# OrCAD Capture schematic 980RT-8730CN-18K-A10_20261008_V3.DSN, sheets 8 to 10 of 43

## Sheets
8 P0021_S2_DUT1: size Custom
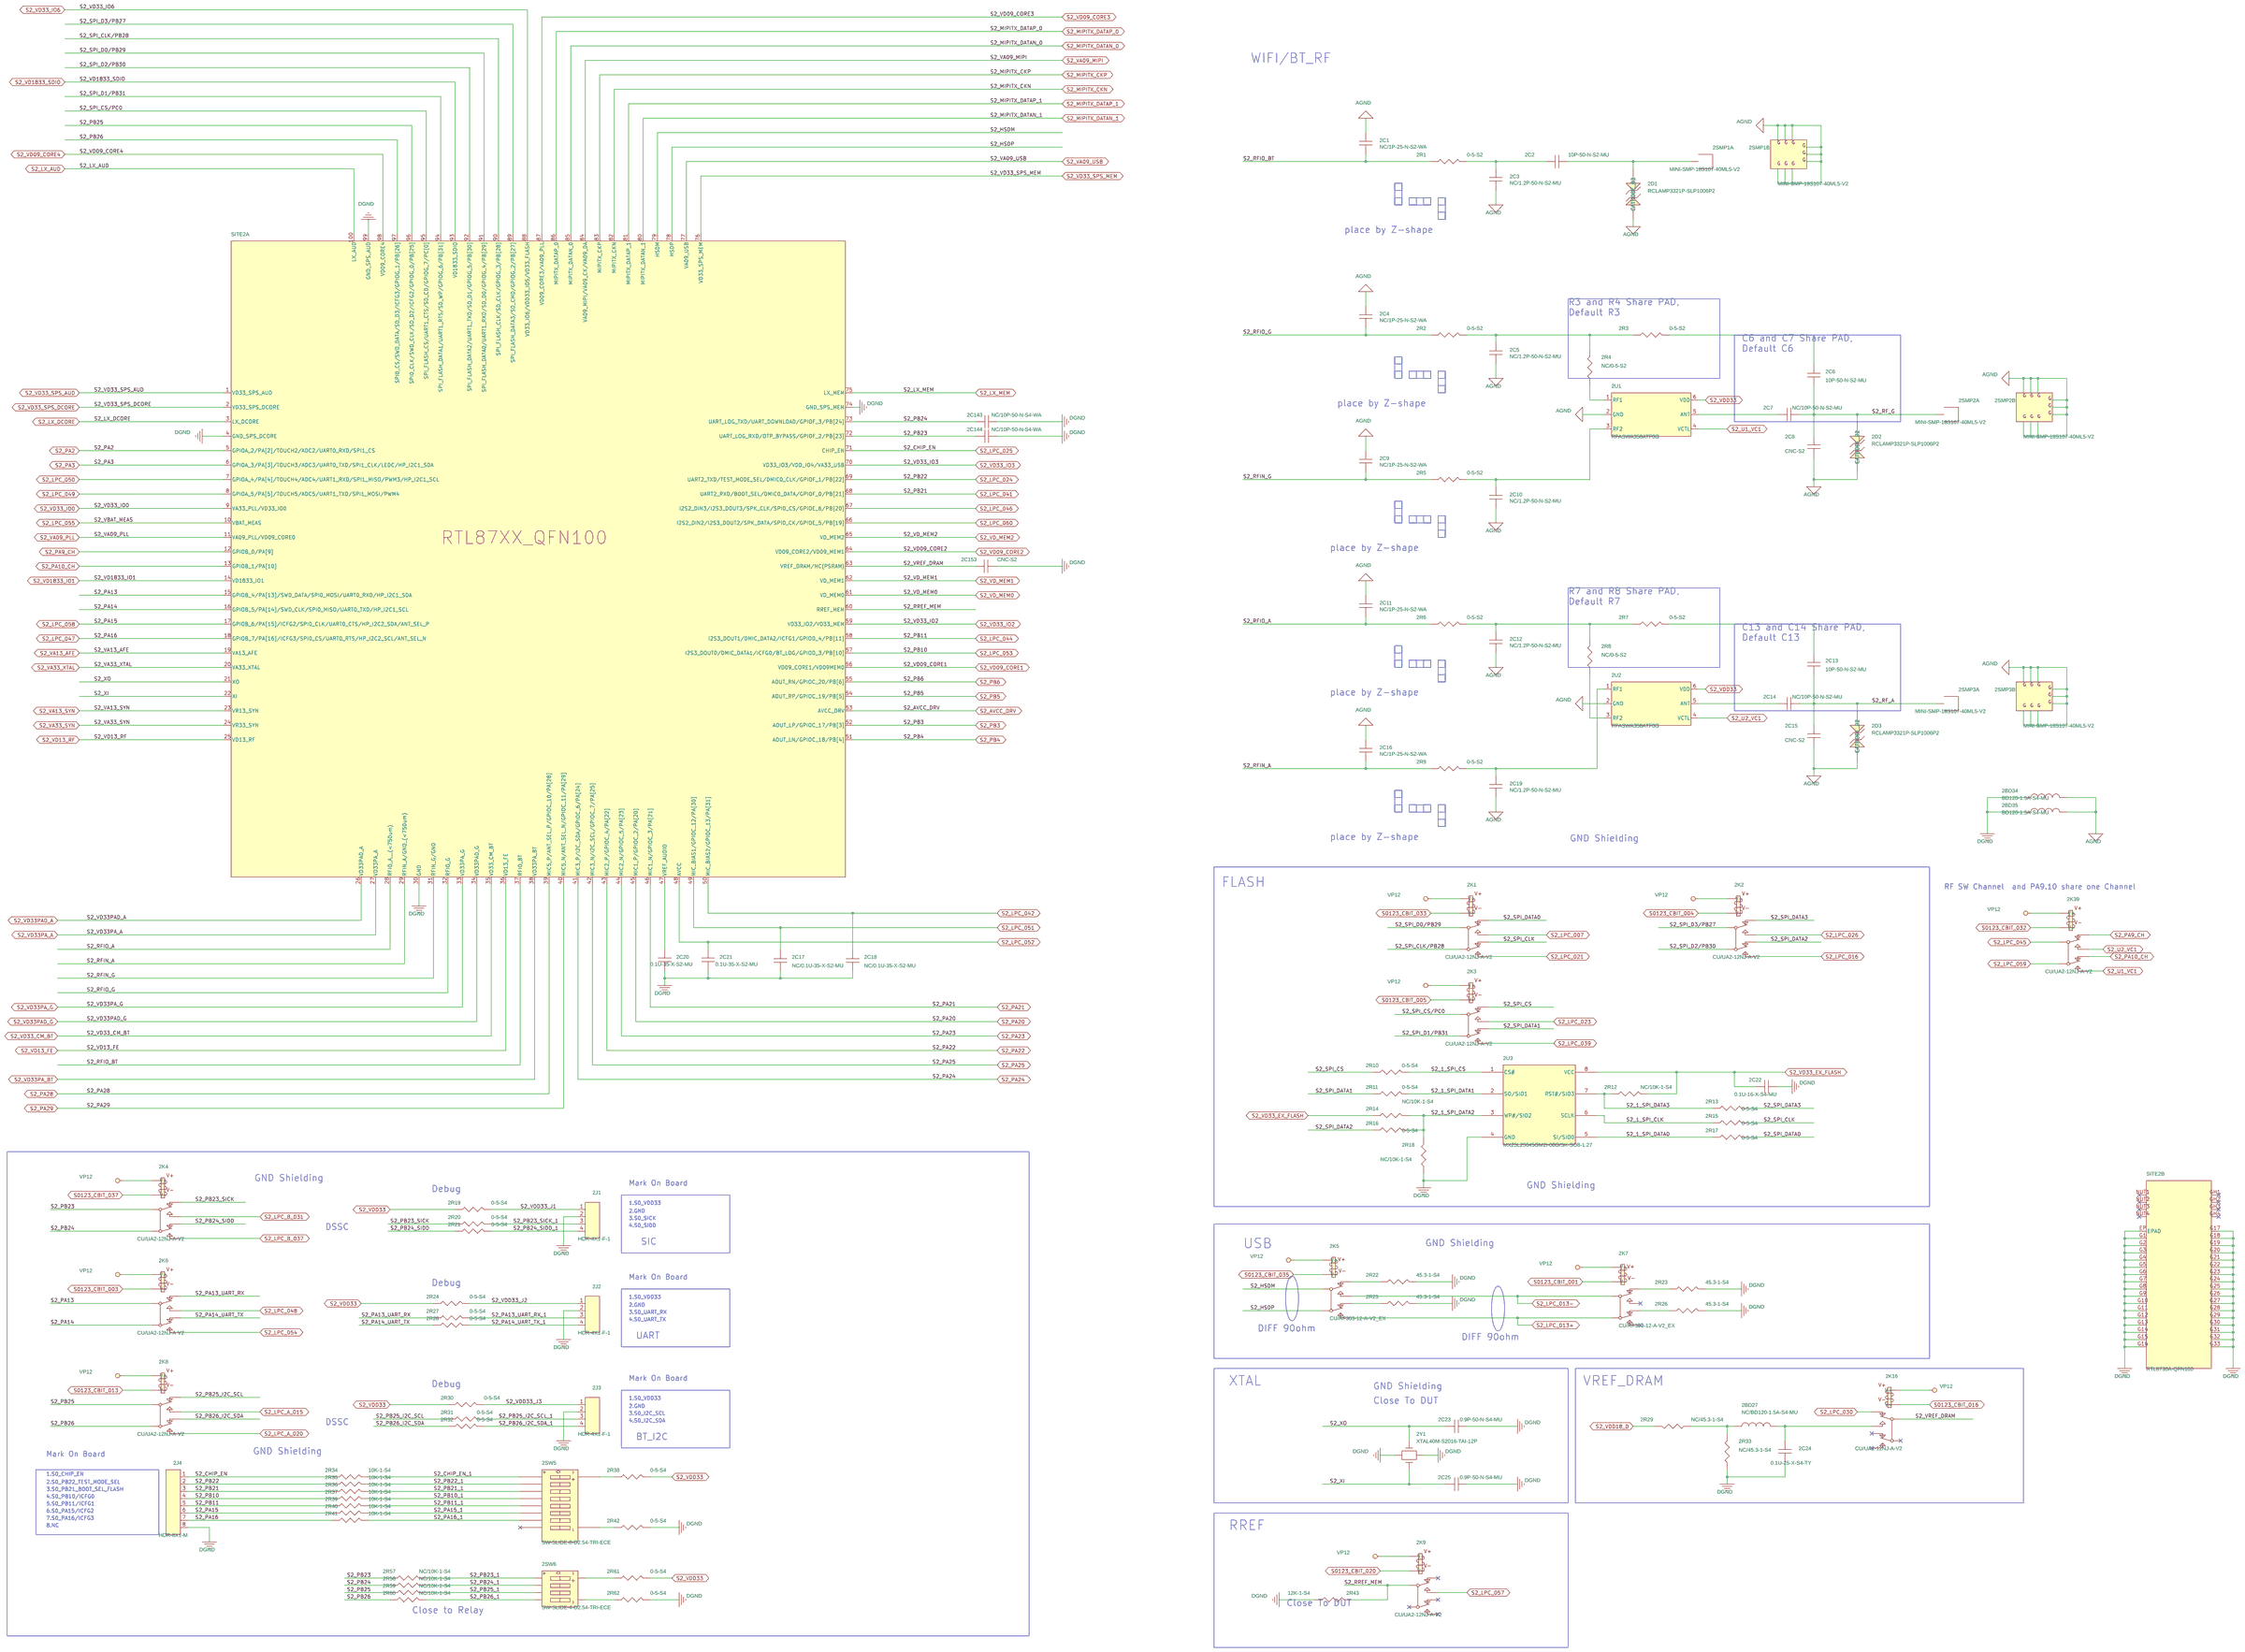
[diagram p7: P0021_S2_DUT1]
9 P0022_S2_Function-test: size A3
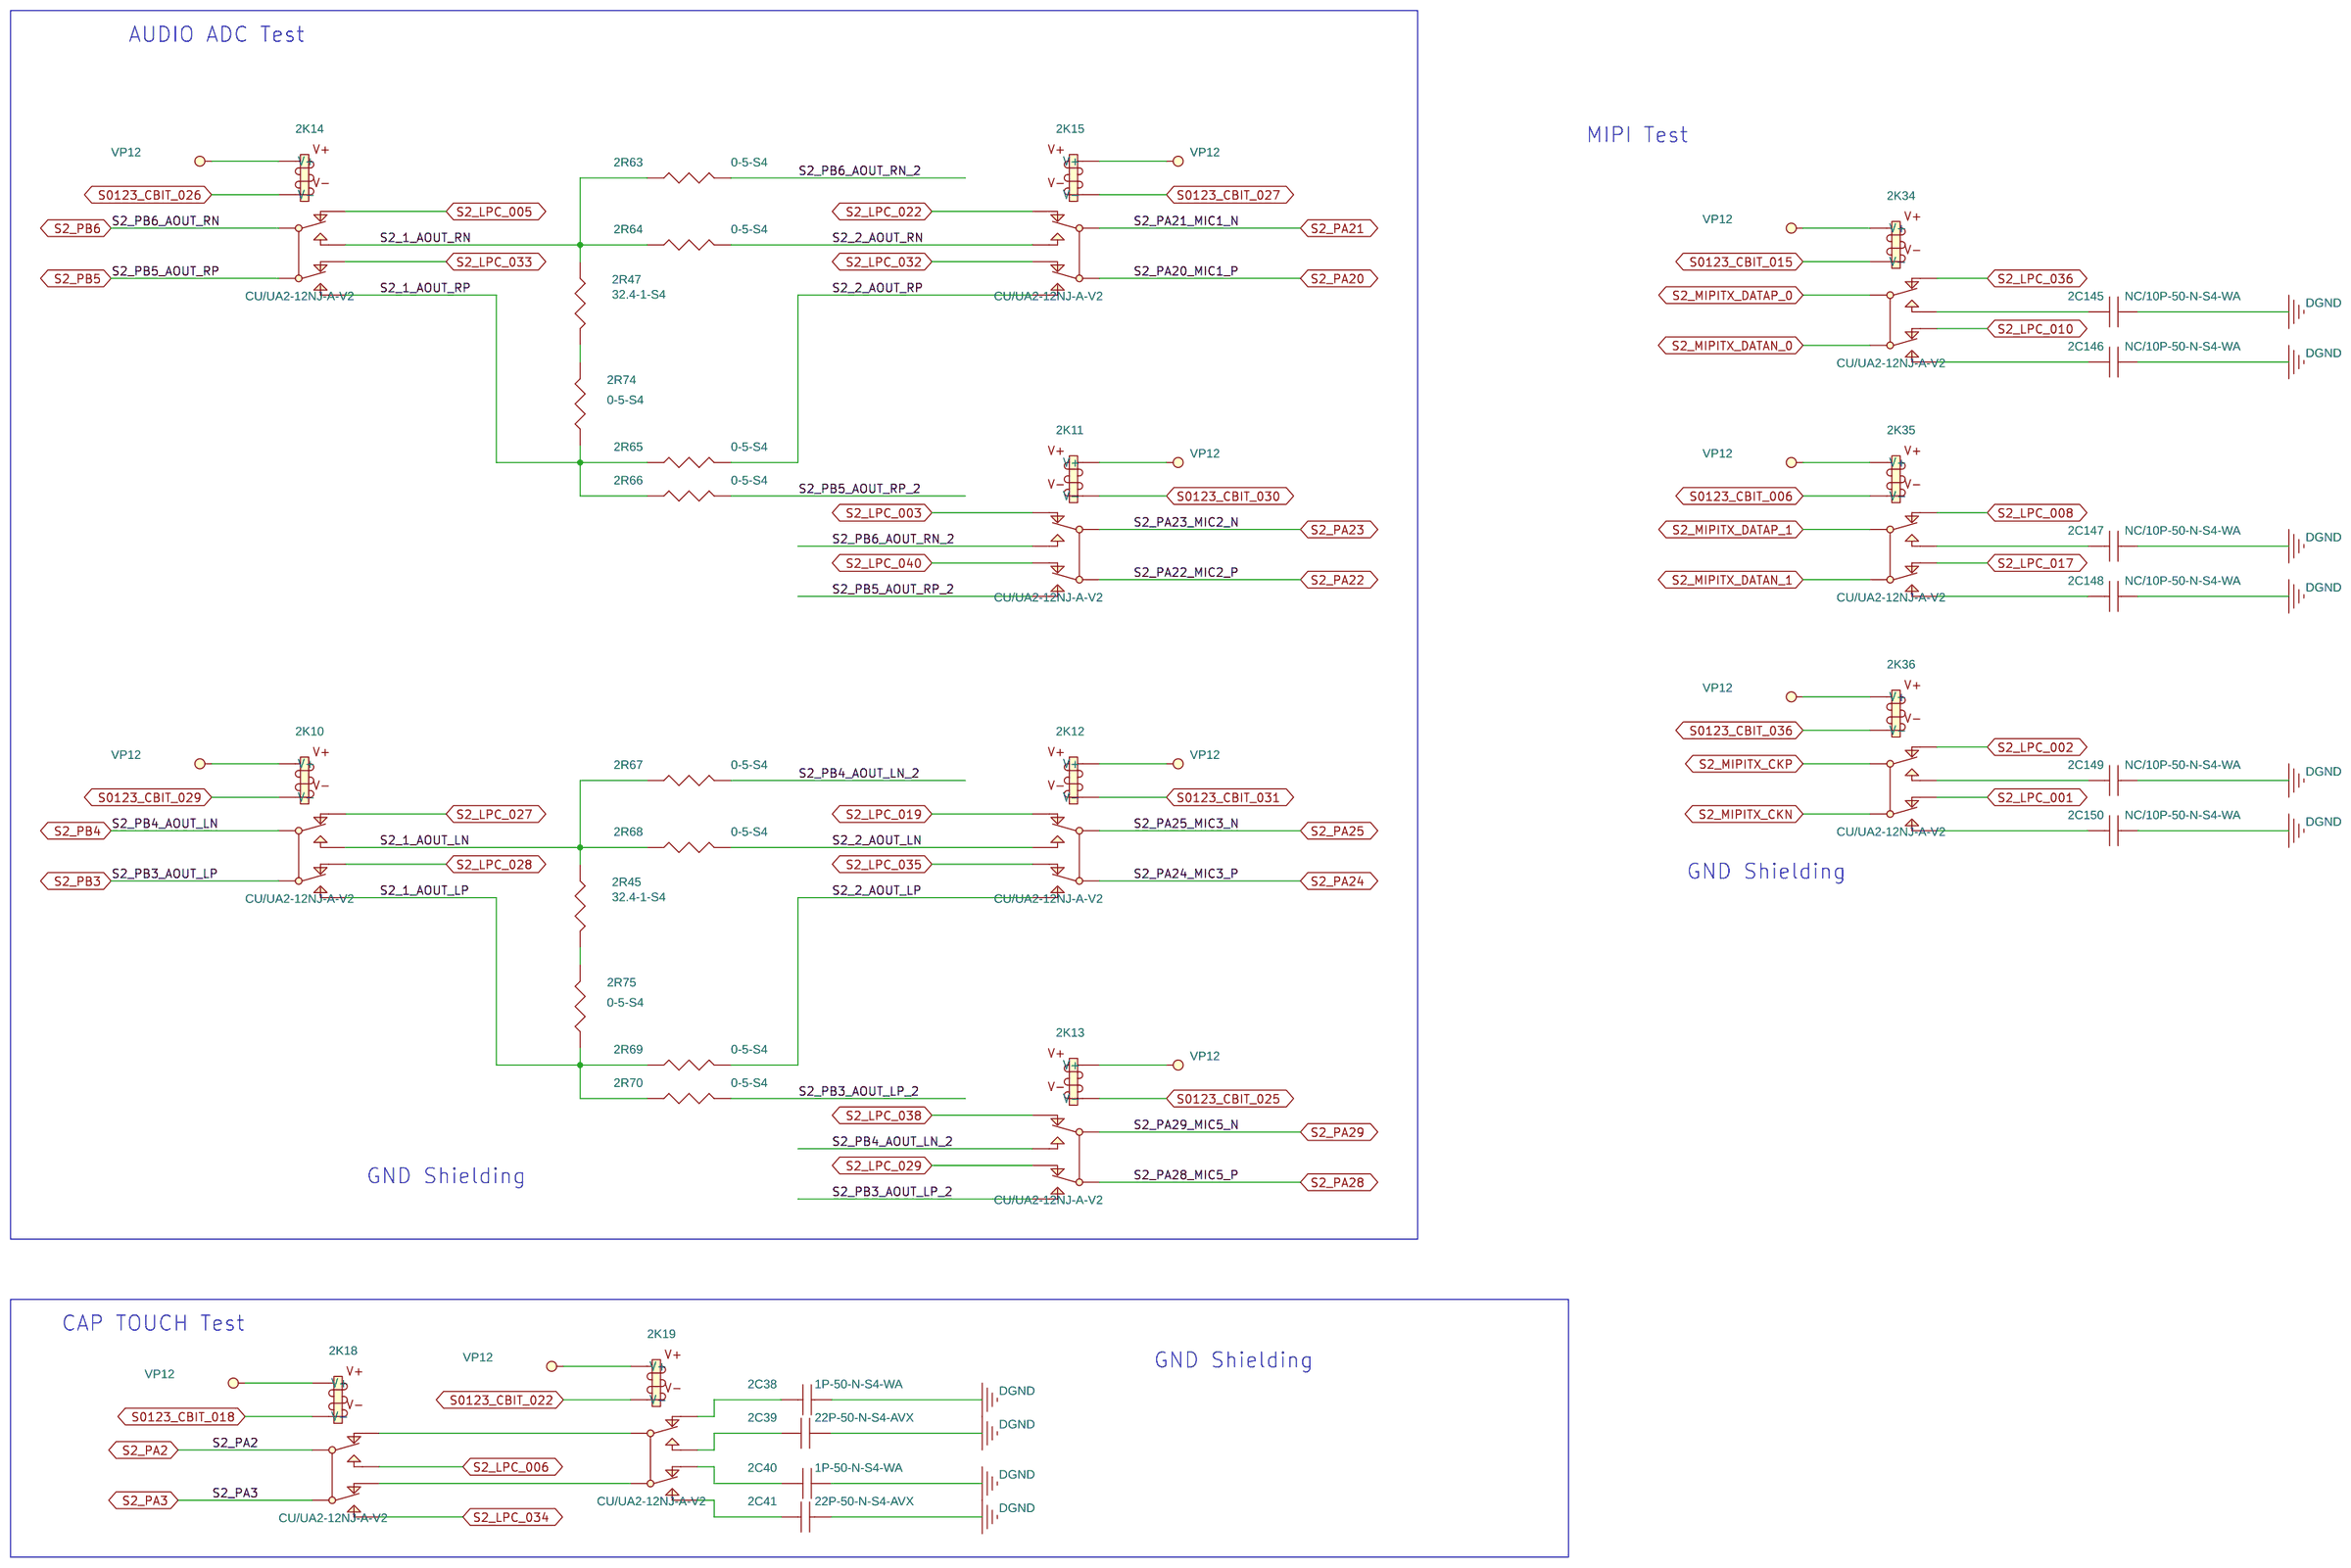
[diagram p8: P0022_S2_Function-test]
10 P0023_S2_Power: size A1
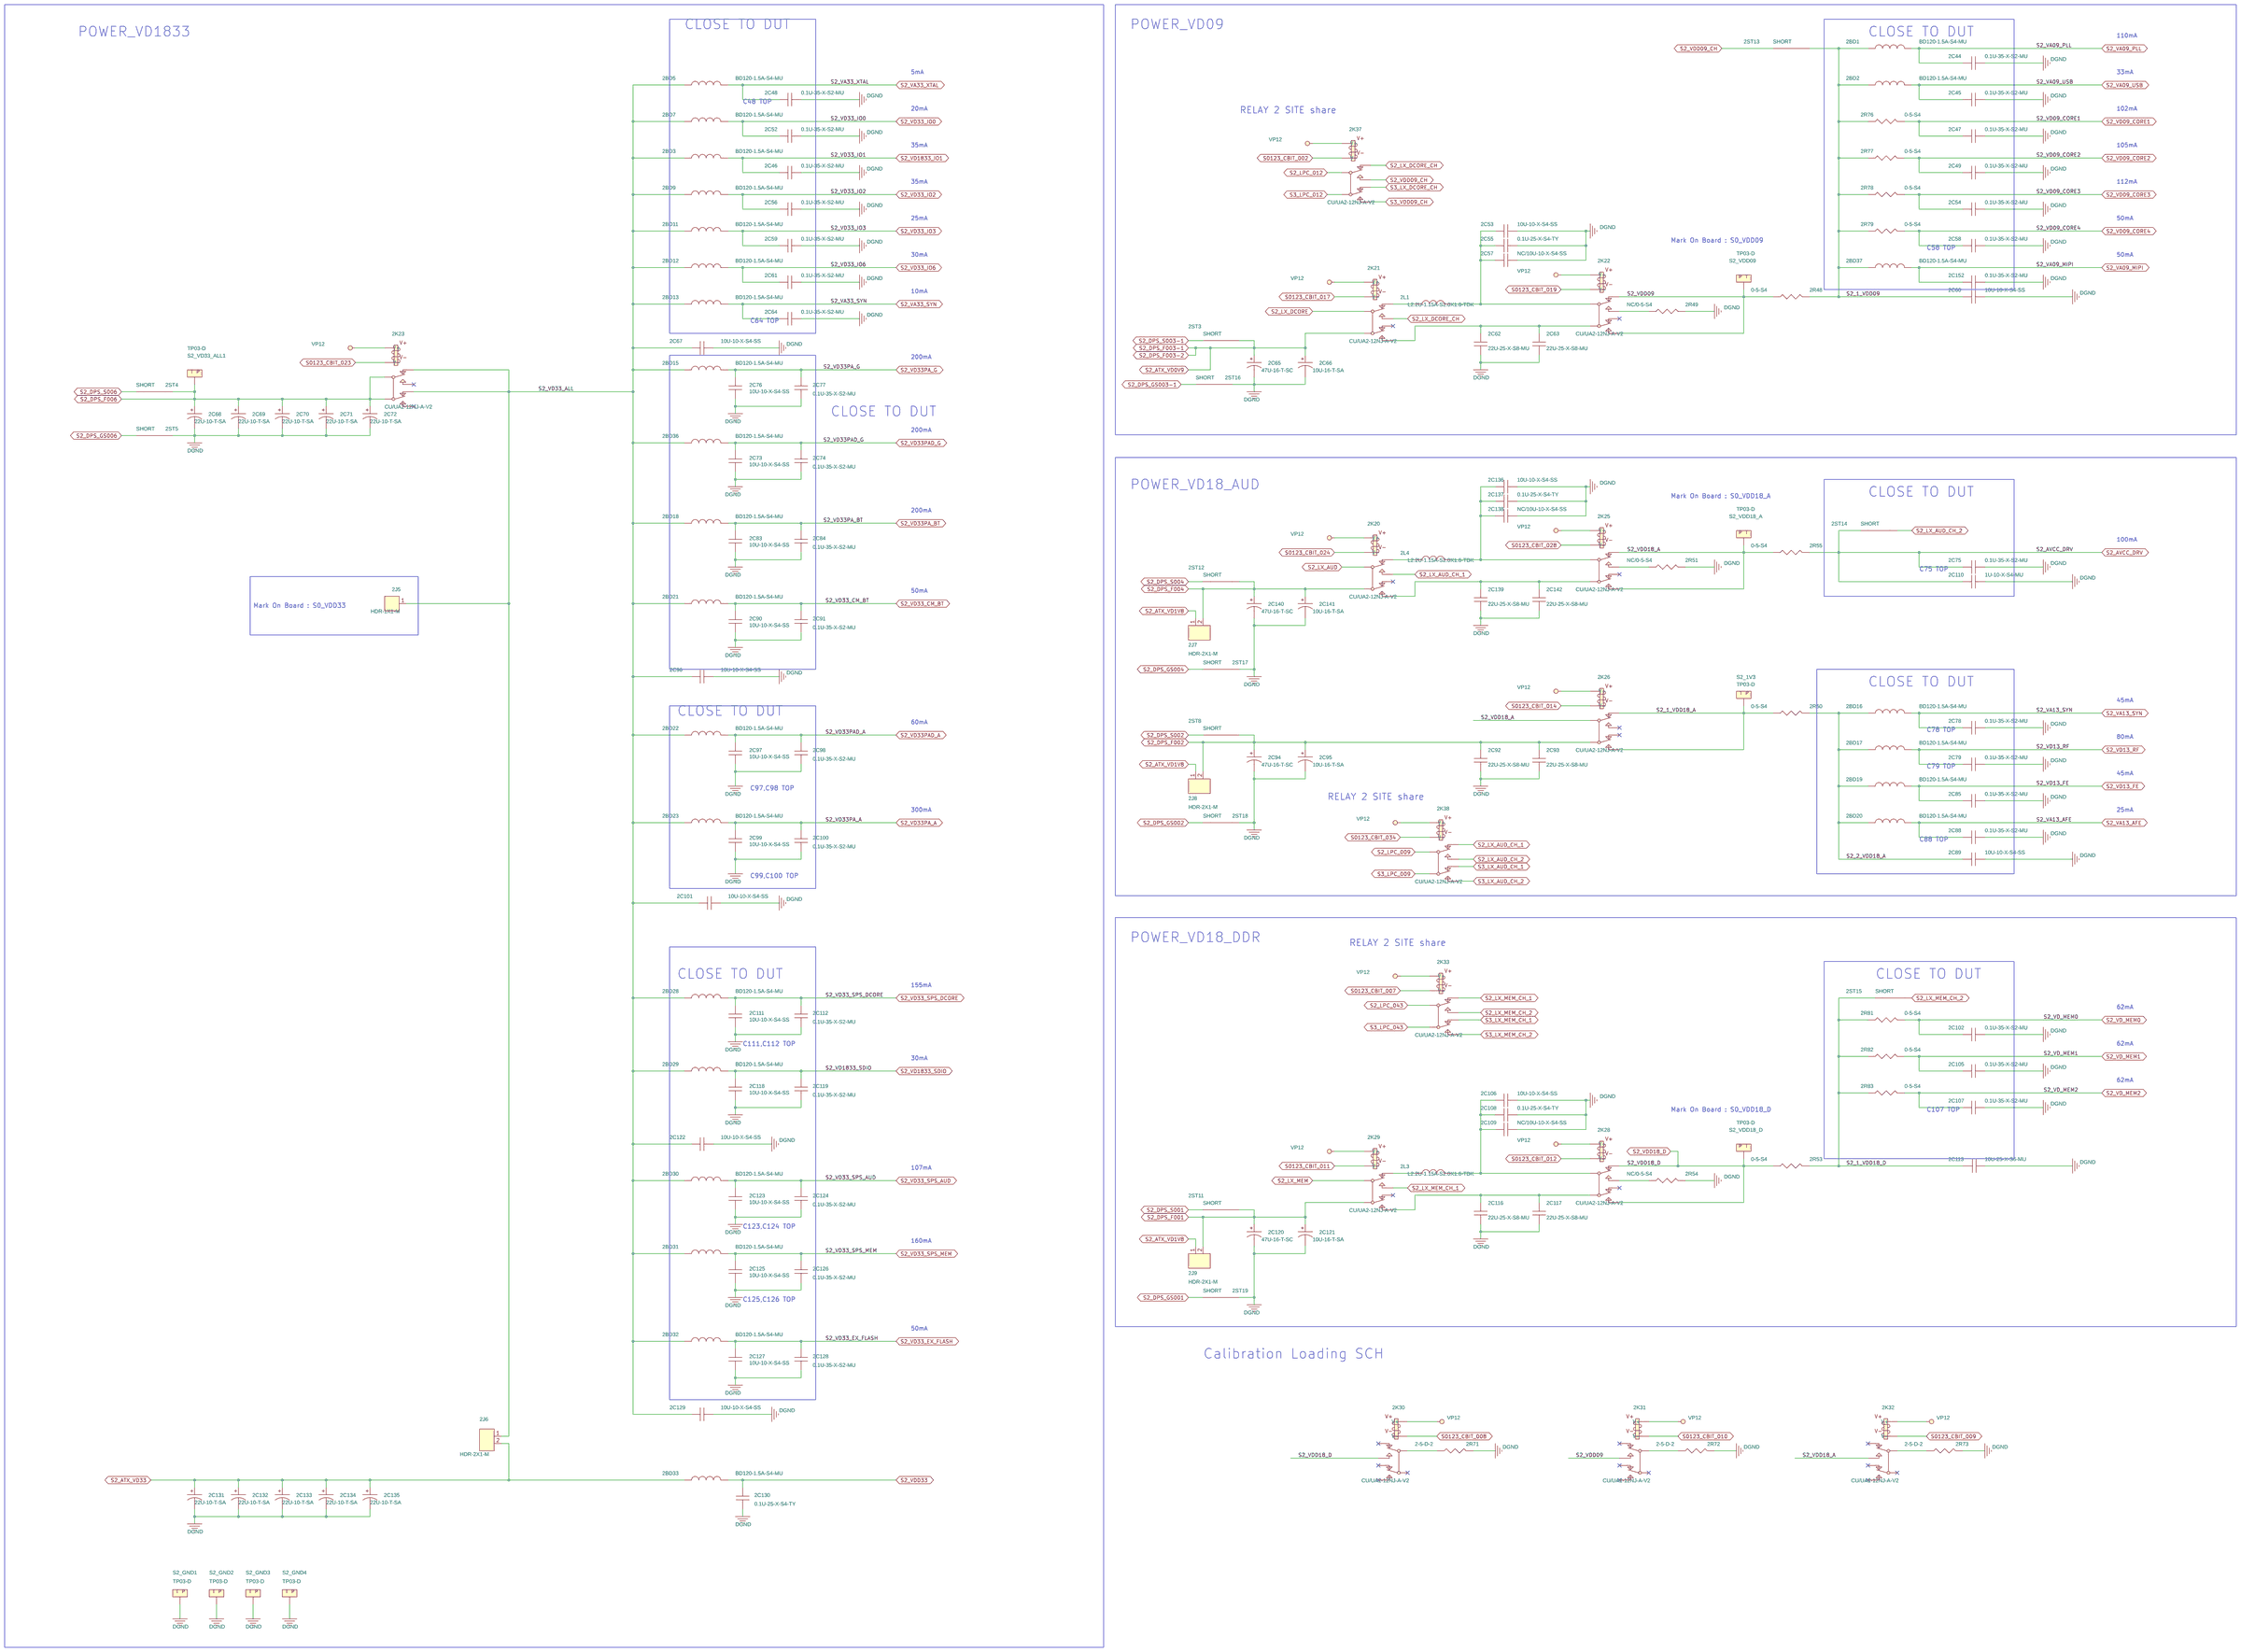
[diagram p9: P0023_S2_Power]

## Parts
sheet P0021_S2_DUT1
2BD27  NC/BD120-1.5A-S4-MU  [FB0402]
2BD34  BD120-1.5A-S4-MU  [FB0402]
2BD35  BD120-1.5A-S4-MU  [FB0402]
2C1  NC/1P-25-N-S2-WA  [C0201]
2C2  10P-50-N-S2-MU  [C0201]
2C3  NC/1.2P-50-N-S2-MU  [C0201]
2C4  NC/1P-25-N-S2-WA  [C0201]
2C5  NC/1.2P-50-N-S2-MU  [C0201]
2C6  10P-50-N-S2-MU  [C0201]
2C7  NC/10P-50-N-S2-MU  [C0201]
2C8  CNC-S2  [C0201]
2C9  NC/1P-25-N-S2-WA  [C0201]
2C10  NC/1.2P-50-N-S2-MU  [C0201]
2C11  NC/1P-25-N-S2-WA  [C0201]
2C12  NC/1.2P-50-N-S2-MU  [C0201]
2C13  10P-50-N-S2-MU  [C0201]
2C14  NC/10P-50-N-S2-MU  [C0201]
2C15  CNC-S2  [C0201]
2C16  NC/1P-25-N-S2-WA  [C0201]
2C17  NC/0.1U-35-X-S2-MU  [C0201]
2C18  NC/0.1U-35-X-S2-MU  [C0201]
2C19  NC/1.2P-50-N-S2-MU  [C0201]
2C20  0.1U-35-X-S2-MU  [C0201]
2C21  0.1U-35-X-S2-MU  [C0201]
2C22  0.1U-16-X-S4-MU  [C0402]
2C23  0.9P-50-N-S4-MU  [C0402]
2C24  0.1U-25-X-S4-TY  [C0402]
2C25  0.9P-50-N-S4-MU  [C0402]
2C143  NC/10P-50-N-S4-WA  [C0402]
2C144  NC/10P-50-N-S4-WA  [C0402]
2C153  CNC-S2  [C0201]
2D1  RCLAMP3321P-SLP1006P2  [DIODE_1X0P6MM]
2D2  RCLAMP3321P-SLP1006P2  [DIODE_1X0P6MM]
2D3  RCLAMP3321P-SLP1006P2  [DIODE_1X0P6MM]
2J1  HDR-4X1-F-1  [CONN_4X1_2P54MM_FL10P5MM]
2J2  HDR-4X1-F-1  [CONN_4X1_2P54MM_FL10P5MM]
2J3  HDR-4X1-F-1  [CONN_4X1_2P54MM_FL10P5MM]
2J4  HDR-8X1-M  [JP_8P_100]
2K1  CU/UA2-12NJ-A-V2  [RL_NECUA2_12V_V2]
2K2  CU/UA2-12NJ-A-V2  [RL_NECUA2_12V_V2]
2K3  CU/UA2-12NJ-A-V2  [RL_NECUA2_12V_V2]
2K4  CU/UA2-12NJ-A-V2  [RL_NECUA2_12V_V2]
2K5  CU/RF303-12-A-V2_EX  [RL_RF303_12V_V2]
2K6  CU/UA2-12NJ-A-V2  [RL_NECUA2_12V_V2]
2K7  CU/RF303-12-A-V2_EX  [RL_RF303_12V_V2]
2K8  CU/UA2-12NJ-A-V2  [RL_NECUA2_12V_V2]
2K9  CU/UA2-12NJ-A-V2  [RL_NECUA2_12V_V2]
2K16  CU/UA2-12NJ-A-V2  [RL_NECUA2_12V_V2]
2K39  CU/UA2-12NJ-A-V2  [RL_NECUA2_12V_V2]
2R1  0-5-S2  [R0201]
2R2  0-5-S2  [R0201]
2R3  0-5-S2  [R0201]
2R4  NC/0-5-S2  [R0201]
2R5  0-5-S2  [R0201]
2R6  0-5-S2  [R0201]
2R7  0-5-S2  [R0201]
2R8  NC/0-5-S2  [R0201]
2R9  0-5-S2  [R0201]
2R10  0-5-S4  [R0402]
2R11  0-5-S4  [R0402]
2R12  NC/10K-1-S4  [R0402]
2R13  0-5-S4  [R0402]
2R14  NC/10K-1-S4  [R0402]
2R15  0-5-S4  [R0402]
2R16  0-5-S4  [R0402]
2R17  0-5-S4  [R0402]
2R18  NC/10K-1-S4  [R0402]
2R19  0-5-S4  [R0402]
2R20  0-5-S4  [R0402]
2R21  0-5-S4  [R0402]
2R22  45.3-1-S4  [R0402]
2R23  45.3-1-S4  [R0402]
2R24  0-5-S4  [R0402]
2R25  45.3-1-S4  [R0402]
2R26  45.3-1-S4  [R0402]
2R27  0-5-S4  [R0402]
2R28  0-5-S4  [R0402]
2R29  NC/45.3-1-S4  [R0402]
2R30  0-5-S4  [R0402]
2R31  0-5-S4  [R0402]
2R32  0-5-S4  [R0402]
2R33  NC/45.3-1-S4  [R0402]
2R34  10K-1-S4  [R0402]
2R35  10K-1-S4  [R0402]
2R36  10K-1-S4  [R0402]
2R37  10K-1-S4  [R0402]
2R38  0-5-S4  [R0402]
2R39  10K-1-S4  [R0402]
2R40  10K-1-S4  [R0402]
2R41  10K-1-S4  [R0402]
2R42  0-5-S4  [R0402]
2R43  12K-1-S4  [R0402]
2R57  NC/10K-1-S4  [R0402]
2R58  NC/10K-1-S4  [R0402]
2R59  NC/10K-1-S4  [R0402]
2R60  NC/10K-1-S4  [R0402]
2R61  0-5-S4  [R0402]
2R62  0-5-S4  [R0402]
2SMP1  MINI-SMP-18S107-40ML5-V2  [CONN_SMP_18S107]  (sections A,B)
2SMP2  MINI-SMP-18S107-40ML5-V2  [CONN_SMP_18S107]  (sections A,B)
2SMP3  MINI-SMP-18S107-40ML5-V2  [CONN_SMP_18S107]  (sections A,B)
2SW5  SW-SLIDE-8-D2.54-TRI-ECE  [SW_DIPX8P_2P54_MM_V2]
2SW6  SW-SLIDE-4-D2.54-TRI-ECE  [SW_DIPX4P_2P54MM_ETD]
2U1  RFASWA358ATF0G  [RF_SW_GW2159_6P]
2U2  RFASWA358ATF0G  [RF_SW_GW2159_6P]
2U3  MX25L25645GM2I-08G/SK-SO8-1.27  [SK_SO8_1P27MM_LOTES]
2Y1  XTAL40M-S2016-TAI-12P  [XTAL_2X1P6MM_4P_0P8MM]
SITE2  RTL8730A-QFN100  [SK_QFN100P_0P35MM_MJC_L8730A]  (sections A,B)
sheet P0022_S2_Function-test
2C38  1P-50-N-S4-WA  [C0402]
2C39  22P-50-N-S4-AVX  [C0402]
2C40  1P-50-N-S4-WA  [C0402]
2C41  22P-50-N-S4-AVX  [C0402]
2C145  NC/10P-50-N-S4-WA  [C0402]
2C146  NC/10P-50-N-S4-WA  [C0402]
2C147  NC/10P-50-N-S4-WA  [C0402]
2C148  NC/10P-50-N-S4-WA  [C0402]
2C149  NC/10P-50-N-S4-WA  [C0402]
2C150  NC/10P-50-N-S4-WA  [C0402]
2K10  CU/UA2-12NJ-A-V2  [RL_NECUA2_12V_V2]
2K11  CU/UA2-12NJ-A-V2  [RL_NECUA2_12V_V2]
2K12  CU/UA2-12NJ-A-V2  [RL_NECUA2_12V_V2]
2K13  CU/UA2-12NJ-A-V2  [RL_NECUA2_12V_V2]
2K14  CU/UA2-12NJ-A-V2  [RL_NECUA2_12V_V2]
2K15  CU/UA2-12NJ-A-V2  [RL_NECUA2_12V_V2]
2K18  CU/UA2-12NJ-A-V2  [RL_NECUA2_12V_V2]
2K19  CU/UA2-12NJ-A-V2  [RL_NECUA2_12V_V2]
2K34  CU/UA2-12NJ-A-V2  [RL_NECUA2_12V_V2]
2K35  CU/UA2-12NJ-A-V2  [RL_NECUA2_12V_V2]
2K36  CU/UA2-12NJ-A-V2  [RL_NECUA2_12V_V2]
2R45  32.4-1-S4  [R0402]
2R47  32.4-1-S4  [R0402]
2R63  0-5-S4  [R0402]
2R64  0-5-S4  [R0402]
2R65  0-5-S4  [R0402]
2R66  0-5-S4  [R0402]
2R67  0-5-S4  [R0402]
2R68  0-5-S4  [R0402]
2R69  0-5-S4  [R0402]
2R70  0-5-S4  [R0402]
2R74  0-5-S4  [R0402]
2R75  0-5-S4  [R0402]
sheet P0023_S2_Power
2BD1  BD120-1.5A-S4-MU  [FB0402]
2BD2  BD120-1.5A-S4-MU  [FB0402]
2BD3  BD120-1.5A-S4-MU  [FB0402]
2BD5  BD120-1.5A-S4-MU  [FB0402]
2BD7  BD120-1.5A-S4-MU  [FB0402]
2BD9  BD120-1.5A-S4-MU  [FB0402]
2BD11  BD120-1.5A-S4-MU  [FB0402]
2BD12  BD120-1.5A-S4-MU  [FB0402]
2BD13  BD120-1.5A-S4-MU  [FB0402]
2BD15  BD120-1.5A-S4-MU  [FB0402]
2BD16  BD120-1.5A-S4-MU  [FB0402]
2BD17  BD120-1.5A-S4-MU  [FB0402]
2BD18  BD120-1.5A-S4-MU  [FB0402]
2BD19  BD120-1.5A-S4-MU  [FB0402]
2BD20  BD120-1.5A-S4-MU  [FB0402]
2BD21  BD120-1.5A-S4-MU  [FB0402]
2BD22  BD120-1.5A-S4-MU  [FB0402]
2BD23  BD120-1.5A-S4-MU  [FB0402]
2BD28  BD120-1.5A-S4-MU  [FB0402]
2BD29  BD120-1.5A-S4-MU  [FB0402]
2BD30  BD120-1.5A-S4-MU  [FB0402]
2BD31  BD120-1.5A-S4-MU  [FB0402]
2BD32  BD120-1.5A-S4-MU  [FB0402]
2BD33  BD120-1.5A-S4-MU  [FB0402]
2BD36  BD120-1.5A-S4-MU  [FB0402]
2BD37  BD120-1.5A-S4-MU  [FB0402]
2C44  0.1U-35-X-S2-MU  [C0201]
2C45  0.1U-35-X-S2-MU  [C0201]
2C46  0.1U-35-X-S2-MU  [C0201]
2C47  0.1U-35-X-S2-MU  [C0201]
2C48  0.1U-35-X-S2-MU  [C0201]
2C49  0.1U-35-X-S2-MU  [C0201]
2C52  0.1U-35-X-S2-MU  [C0201]
2C53  10U-10-X-S4-SS  [C0402]
2C54  0.1U-35-X-S2-MU  [C0201]
2C55  0.1U-25-X-S4-TY  [C0402]
2C56  0.1U-35-X-S2-MU  [C0201]
2C57  NC/10U-10-X-S4-SS  [C0402]
2C58  0.1U-35-X-S2-MU  [C0201]
2C59  0.1U-35-X-S2-MU  [C0201]
2C60  10U-10-X-S4-SS  [C0402]
2C61  0.1U-35-X-S2-MU  [C0201]
2C62  22U-25-X-S8-MU  [C0805]
2C63  22U-25-X-S8-MU  [C0805]
2C64  0.1U-35-X-S2-MU  [C0201]
2C65  47U-16-T-SC  [CODE_C]
2C66  10U-16-T-SA  [CODE_A]
2C67  10U-10-X-S4-SS  [C0402]
2C68  22U-10-T-SA  [CODE_A]
2C69  22U-10-T-SA  [CODE_A]
2C70  22U-10-T-SA  [CODE_A]
2C71  22U-10-T-SA  [CODE_A]
2C72  22U-10-T-SA  [CODE_A]
2C73  10U-10-X-S4-SS  [C0402]
2C74  0.1U-35-X-S2-MU  [C0201]
2C75  0.1U-35-X-S2-MU  [C0201]
2C76  10U-10-X-S4-SS  [C0402]
2C77  0.1U-35-X-S2-MU  [C0201]
2C78  0.1U-35-X-S2-MU  [C0201]
2C79  0.1U-35-X-S2-MU  [C0201]
2C83  10U-10-X-S4-SS  [C0402]
2C84  0.1U-35-X-S2-MU  [C0201]
2C85  0.1U-35-X-S2-MU  [C0201]
2C88  0.1U-35-X-S2-MU  [C0201]
2C89  10U-10-X-S4-SS  [C0402]
2C90  10U-10-X-S4-SS  [C0402]
2C91  0.1U-35-X-S2-MU  [C0201]
2C92  22U-25-X-S8-MU  [C0805]
2C93  22U-25-X-S8-MU  [C0805]
2C94  47U-16-T-SC  [CODE_C]
2C95  10U-16-T-SA  [CODE_A]
2C96  10U-10-X-S4-SS  [C0402]
2C97  10U-10-X-S4-SS  [C0402]
2C98  0.1U-35-X-S2-MU  [C0201]
2C99  10U-10-X-S4-SS  [C0402]
2C100  0.1U-35-X-S2-MU  [C0201]
2C101  10U-10-X-S4-SS  [C0402]
2C102  0.1U-35-X-S2-MU  [C0201]
2C105  0.1U-35-X-S2-MU  [C0201]
2C106  10U-10-X-S4-SS  [C0402]
2C107  0.1U-35-X-S2-MU  [C0201]
2C108  0.1U-25-X-S4-TY  [C0402]
2C109  NC/10U-10-X-S4-SS  [C0402]
2C110  1U-10-X-S4-MU  [C0402]
2C111  10U-10-X-S4-SS  [C0402]
2C112  0.1U-35-X-S2-MU  [C0201]
2C113  10U-25-X-S6-MU  [C0603]
2C116  22U-25-X-S8-MU  [C0805]
2C117  22U-25-X-S8-MU  [C0805]
2C118  10U-10-X-S4-SS  [C0402]
2C119  0.1U-35-X-S2-MU  [C0201]
2C120  47U-16-T-SC  [CODE_C]
2C121  10U-16-T-SA  [CODE_A]
2C122  10U-10-X-S4-SS  [C0402]
2C123  10U-10-X-S4-SS  [C0402]
2C124  0.1U-35-X-S2-MU  [C0201]
2C125  10U-10-X-S4-SS  [C0402]
2C126  0.1U-35-X-S2-MU  [C0201]
2C127  10U-10-X-S4-SS  [C0402]
2C128  0.1U-35-X-S2-MU  [C0201]
2C129  10U-10-X-S4-SS  [C0402]
2C130  0.1U-25-X-S4-TY  [C0402]
2C131  22U-10-T-SA  [CODE_A]
2C132  22U-10-T-SA  [CODE_A]
2C133  22U-10-T-SA  [CODE_A]
2C134  22U-10-T-SA  [CODE_A]
2C135  22U-10-T-SA  [CODE_A]
2C136  10U-10-X-S4-SS  [C0402]
2C137  0.1U-25-X-S4-TY  [C0402]
2C138  NC/10U-10-X-S4-SS  [C0402]
2C139  22U-25-X-S8-MU  [C0805]
2C140  47U-16-T-SC  [CODE_C]
2C141  10U-16-T-SA  [CODE_A]
2C142  22U-25-X-S8-MU  [C0805]
2C152  0.1U-35-X-S2-MU  [C0201]
2J5  HDR-1X1-M  [JP_1P_RD070_040]
2J6  HDR-2X1-M  [JP_2P_100]
2J7  HDR-2X1-M  [JP_2P_100]
2J8  HDR-2X1-M  [JP_2P_100]
2J9  HDR-2X1-M  [JP_2P_100]
2K20  CU/UA2-12NJ-A-V2  [RL_NECUA2_12V_V2]
2K21  CU/UA2-12NJ-A-V2  [RL_NECUA2_12V_V2]
2K22  CU/UA2-12NJ-A-V2  [RL_NECUA2_12V_V2]
2K23  CU/UA2-12NJ-A-V2  [RL_NECUA2_12V_V2]
2K25  CU/UA2-12NJ-A-V2  [RL_NECUA2_12V_V2]
2K26  CU/UA2-12NJ-A-V2  [RL_NECUA2_12V_V2]
2K28  CU/UA2-12NJ-A-V2  [RL_NECUA2_12V_V2]
2K29  CU/UA2-12NJ-A-V2  [RL_NECUA2_12V_V2]
2K30  CU/UA2-12NJ-A-V2  [RL_NECUA2_12V_V2]
2K31  CU/UA2-12NJ-A-V2  [RL_NECUA2_12V_V2]
2K32  CU/UA2-12NJ-A-V2  [RL_NECUA2_12V_V2]
2K33  CU/UA2-12NJ-A-V2  [RL_NECUA2_12V_V2]
2K37  CU/UA2-12NJ-A-V2  [RL_NECUA2_12V_V2]
2K38  CU/UA2-12NJ-A-V2  [RL_NECUA2_12V_V2]
2L1  L2.2U-1.15A-S2.0X1.6-TDK  [IND_VL252012E]
2L3  L2.2U-1.15A-S2.0X1.6-TDK  [IND_VL252012E]
2L4  L2.2U-1.15A-S2.0X1.6-TDK  [IND_VL252012E]
2R48  0-5-S4  [R0402]
2R49  NC/0-5-S4  [R0402]
2R50  0-5-S4  [R0402]
2R51  NC/0-5-S4  [R0402]
2R53  0-5-S4  [R0402]
2R54  NC/0-5-S4  [R0402]
2R55  0-5-S4  [R0402]
2R71  2-5-D-2  [RC02W_27MM]
2R72  2-5-D-2  [RC02W_27MM]
2R73  2-5-D-2  [RC02W_27MM]
2R76  0-5-S4  [R0402]
2R77  0-5-S4  [R0402]
2R78  0-5-S4  [R0402]
2R79  0-5-S4  [R0402]
2R81  0-5-S4  [R0402]
2R82  0-5-S4  [R0402]
2R83  0-5-S4  [R0402]
2ST3  SHORT  [DEFAULT_SHORT_SMALL]
2ST4  SHORT  [DEFAULT_SHORT_SMALL]
2ST5  SHORT  [DEFAULT_SHORT_SMALL]
2ST8  SHORT  [DEFAULT_SHORT_SMALL]
2ST11  SHORT  [DEFAULT_SHORT_SMALL]
2ST12  SHORT  [DEFAULT_SHORT_SMALL]
2ST13  SHORT  [DEFAULT_SHORT_SMALL]
2ST14  SHORT  [DEFAULT_SHORT_SMALL]
2ST15  SHORT  [DEFAULT_SHORT_SMALL]
2ST16  SHORT  [DEFAULT_SHORT_SMALL]
2ST17  SHORT  [DEFAULT_SHORT_SMALL]
2ST18  SHORT  [DEFAULT_SHORT_SMALL]
2ST19  SHORT  [DEFAULT_SHORT_SMALL]
S2_1V3  TP03-D  [TP_060_040]
S2_GND1  TP03-D  [TP_060_040]
S2_GND2  TP03-D  [TP_060_040]
S2_GND3  TP03-D  [TP_060_040]
S2_GND4  TP03-D  [TP_060_040]
S2_VD33_ALL1  TP03-D  [TP_060_040]
S2_VDD09  TP03-D  [TP_060_040]
S2_VDD18_A  TP03-D  [TP_060_040]
S2_VDD18_D  TP03-D  [TP_060_040]

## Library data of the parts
2BD27 = BD120-1.5A-S4-MU: KAIROSNAME: BD27
2BD34 = BD120-1.5A-S4-MU: KAIROSNAME: BD34
2BD35 = BD120-1.5A-S4-MU: KAIROSNAME: BD35
2C1 2C4 2C9 2C11 2C16 = 1P-25-N-S2-WA
2C2 2C6 2C7 2C13 2C14 = 10P-50-N-S2-MU
2C3 2C5 2C10 2C12 2C19 = 1.2P-50-N-S2-MU
2C8 2C15 = CNC-S4
2C17 2C18 2C46 = 0.1U-35-X-S2-MU: KAIROSNAME: C46
2C20 2C21 2C98 = 0.1U-35-X-S2-MU: KAIROSNAME: C98
2C22 = 0.1U-16-X-S4: KAIROSNAME: C22
2C23 = 10P-50-N-S4-MU-1: KAIROSNAME: C23
2C24 = 0.1U-25-X-S4-TY: KAIROSNAME: C24
2C25 = 10P-50-N-S4-MU-1: KAIROSNAME: C25
2C143-2C150 = 10P-50-N-S4-WA
2C48 2C153 = 0.1U-35-X-S2-MU: KAIROSNAME: C48
2D1 = RCLAMP3321P-SLP1006P2: KAIROSNAME: D1
2D2 = RCLAMP3321P-SLP1006P2: KAIROSNAME: D2
2D3 = RCLAMP3321P-SLP1006P2: KAIROSNAME: D3
2J1-2J3 = HDR-4X1-F-1
2J4 = HDR-8X1-M: KAIROSNAME: J4
2K1 2K39 = CU_UA2-12NJ-A-V2: KAIROSNAME: K1
2K2 2K16 = CU_UA2-12NJ-A-V2: KAIROSNAME: K2
2K3 = CU_UA2-12NJ-A-V2: KAIROSNAME: K3
2K4 = CU_UA2-12NJ-A-V2: KAIROSNAME: K4
2K5 = CU_RF303-12-A-V2_EX: KAIROSNAME: K5
2K6 = CU_UA2-12NJ-A-V2: KAIROSNAME: K6
2K7 = CU_RF303-12-A-V2_EX: KAIROSNAME: K7
2K8 = CU_UA2-12NJ-A-V2: KAIROSNAME: K8
2K9 = CU_UA2-12NJ-A-V2: KAIROSNAME: K9
2R1-2R9 = 0-5-S2
2R10 = 0-5-S4: KAIROSNAME: R10
2R11 = 0-5-S4: KAIROSNAME: R11
2R12 = 10K-1-S4: KAIROSNAME: R12
2R13 = 0-5-S4: KAIROSNAME: R13
2R14 = 10K-1-S4: KAIROSNAME: R14
2R15 = 0-5-S4: KAIROSNAME: R15
2R16 = 0-5-S4: KAIROSNAME: R16
2R17 = 0-5-S4: KAIROSNAME: R17
2R18 = 10K-1-S4: KAIROSNAME: R18
2R19 = 0-5-S4: KAIROSNAME: R19
2R20 = 0-5-S4: KAIROSNAME: R20
2R21 = 0-5-S4: KAIROSNAME: R21
2R22 = 45.3-1-S4: KAIROSNAME: R22
2R23 = 45.3-1-S4: KAIROSNAME: R23
2R24 = 0-5-S4: KAIROSNAME: R24
2R25 = 45.3-1-S4: KAIROSNAME: R25
2R26 = 45.3-1-S4: KAIROSNAME: R26
2R27 = 0-5-S4: KAIROSNAME: R27
2R28 = 0-5-S4: KAIROSNAME: R28
2R29 = 45.3-1-S4: KAIROSNAME: R29
2R30 = 0-5-S4: KAIROSNAME: R30
2R31 = 0-5-S4: KAIROSNAME: R31
2R32 = 0-5-S4: KAIROSNAME: R32
2R33 = 45.3-1-S4: KAIROSNAME: R33
2R34 = 10K-1-S4: KAIROSNAME: R34
2R35 = 10K-1-S4: KAIROSNAME: R35
2R36 = 10K-1-S4: KAIROSNAME: R36
2R37 = 10K-1-S4: KAIROSNAME: R37
2R38 = 0-5-S4: KAIROSNAME: R38
2R39 = 10K-1-S4: KAIROSNAME: R39
2R40 = 10K-1-S4: KAIROSNAME: R40
2R41 = 10K-1-S4: KAIROSNAME: R41
2R42 = 0-5-S4: KAIROSNAME: R42
2R43 = 12K-1-S4: KAIROSNAME: R43
2R57 = 10K-1-S4: KAIROSNAME: R57
2R58 = 10K-1-S4: KAIROSNAME: R58
2R59 = 10K-1-S4: KAIROSNAME: R59
2R60 = 10K-1-S4: KAIROSNAME: R60
2R61 = 0-5-S4: KAIROSNAME: R61
2R62 = 0-5-S4: KAIROSNAME: R62
2SMP1 = MINI-SMP-18S107-40ML5-V2: KAIROSNAME: SMP1A
2SMP2 = MINI-SMP-18S107-40ML5-V2: KAIROSNAME: SMP2B
2SMP3 = MINI-SMP-18S107-40ML5-V2: KAIROSNAME: SMP3A
2SW5 = SW-SLIDE-8-D2.54-TRI-ECE
2SW6 = SW-SLIDE-4-D2.54-TRI-ECE
2U1 2U2 = RFASWA358ATF0G
2U3 = MX25R6435FM2IL0-SOP8: KAIROSNAME: U3
2Y1 = XTAL40M-S2016-TAI-12P: KAIROSNAME: Y1
SITE2 = RTL8730A-QFN100
2C38 = 10P-50-N-S4-MU-1: KAIROSNAME: C38
2C39 = 33P-50-N-S4-WA: KAIROSNAME: C39
2C40 = 10P-50-N-S4-MU-1: KAIROSNAME: C40
2C41 = 33P-50-N-S4-WA: KAIROSNAME: C41
2K10 = CU_UA2-12NJ-A-V2: KAIROSNAME: K10
2K11 = CU_UA2-12NJ-A-V2: KAIROSNAME: K11
2K12 = CU_UA2-12NJ-A-V2: KAIROSNAME: K12
2K13 = CU_UA2-12NJ-A-V2: KAIROSNAME: K13
2K14 = CU_UA2-12NJ-A-V2: KAIROSNAME: K14
2K15 2K34-2K36 = CU_UA2-12NJ-A-V2: KAIROSNAME: K15
2K18 = CU_UA2-12NJ-A-V2: KAIROSNAME: K18
2K19 = CU_UA2-12NJ-A-V2: KAIROSNAME: K19
2R45 = 32.4-1-S4: KAIROSNAME: R45
2R47 = 32.4-1-S4: KAIROSNAME: R47
2R63 = 0-5-S4: KAIROSNAME: R63
2R64 = 0-5-S4: KAIROSNAME: R64
2R65 2R74 2R75 = 0-5-S4: KAIROSNAME: R65
2R66 = 0-5-S4: KAIROSNAME: R66
2R67 = 0-5-S4: KAIROSNAME: R67
2R68 = 0-5-S4: KAIROSNAME: R68
2R69 = 0-5-S4: KAIROSNAME: R69
2R70 = 0-5-S4: KAIROSNAME: R70
2BD1 = BD120-1.5A-S4-MU: KAIROSNAME: BD1
2BD2 = BD120-1.5A-S4-MU: KAIROSNAME: BD2
2BD3 = BD120-1.5A-S4-MU: KAIROSNAME: BD3
2BD5 = BD120-1.5A-S4-MU: KAIROSNAME: BD5
2BD7 = BD120-1.5A-S4-MU: KAIROSNAME: BD7
2BD9 = BD120-1.5A-S4-MU: KAIROSNAME: BD9
2BD11 = BD120-1.5A-S4-MU: KAIROSNAME: BD11
2BD12 = BD120-1.5A-S4-MU: KAIROSNAME: BD12
2BD13 = BD120-1.5A-S4-MU: KAIROSNAME: BD13
2BD15 2BD36 = BD120-1.5A-S4-MU: KAIROSNAME: BD15
2BD16 = BD120-1.5A-S4-MU: KAIROSNAME: BD16
2BD17 = BD120-1.5A-S4-MU: KAIROSNAME: BD17
2BD18 = BD120-1.5A-S4-MU: KAIROSNAME: BD18
2BD19 = BD120-1.5A-S4-MU: KAIROSNAME: BD19
2BD20 = BD120-1.5A-S4-MU: KAIROSNAME: BD20
2BD21 = BD120-1.5A-S4-MU: KAIROSNAME: BD21
2BD22 = BD120-1.5A-S4-MU: KAIROSNAME: BD22
2BD23 = BD120-1.5A-S4-MU: KAIROSNAME: BD23
2BD28 = BD120-1.5A-S4-MU: KAIROSNAME: BD28
2BD29 = BD120-1.5A-S4-MU: KAIROSNAME: BD29
2BD30 = BD120-1.5A-S4-MU: KAIROSNAME: BD30
2BD31 = BD120-1.5A-S4-MU: KAIROSNAME: BD31
2BD32 = BD120-1.5A-S4-MU: KAIROSNAME: BD32
2BD33 = BD120-1.5A-S4-MU: KAIROSNAME: BD33
2BD37 = BD120-1.5A-S4-MU: KAIROSNAME: BD10
2C44 = 0.1U-35-X-S2-MU: KAIROSNAME: C44
2C45 = 0.1U-35-X-S2-MU: KAIROSNAME: C45
2C47 = 0.1U-35-X-S2-MU: KAIROSNAME: C47
2C49 = 0.1U-35-X-S2-MU: KAIROSNAME: C49
2C52 = 0.1U-35-X-S2-MU: KAIROSNAME: C52
2C53 = 10U-10-X-S4-SS: KAIROSNAME: C53
2C54 = 0.1U-35-X-S2-MU: KAIROSNAME: C54
2C55 = 0.1U-25-X-S4-TY: KAIROSNAME: C55
2C56 = 0.1U-35-X-S2-MU: KAIROSNAME: C56
2C57 = 10U-10-X-S4-SS: KAIROSNAME: C57
2C58 2C152 = 0.1U-35-X-S2-MU: KAIROSNAME: C58
2C59 = 0.1U-35-X-S2-MU: KAIROSNAME: C59
2C60 = 10U-10-X-S4-SS: KAIROSNAME: C60
2C61 = 0.1U-35-X-S2-MU: KAIROSNAME: C61
2C62 = 22U-25-X-S8-MU: KAIROSNAME: C62
2C63 = 22U-25-X-S8-MU: KAIROSNAME: C63
2C64 = 0.1U-35-X-S2-MU: KAIROSNAME: C64
2C65 = 47U-16-T-SC: KAIROSNAME: C65
2C66 = 10U-16-T-SA: KAIROSNAME: C66
2C67 = 10U-10-X-S4-SS: KAIROSNAME: C67
2C68 = 22U-10-T-SA: KAIROSNAME: C68
2C69 = 22U-10-T-SA: KAIROSNAME: C69
2C70 = 22U-10-T-SA: KAIROSNAME: C70
2C71 = 22U-10-T-SA: KAIROSNAME: C71
2C72 = 22U-10-T-SA: KAIROSNAME: C72
2C73 2C76 = 10U-10-X-S4-SS: KAIROSNAME: C76
2C74 2C77 = 0.1U-35-X-S2-MU: KAIROSNAME: C77
2C75 = 0.1U-35-X-S2-MU: KAIROSNAME: C75
2C78 = 0.1U-35-X-S2-MU: KAIROSNAME: C78
2C79 = 0.1U-35-X-S2-MU: KAIROSNAME: C79
2C83 = 10U-10-X-S4-SS: KAIROSNAME: C83
2C84 = 0.1U-35-X-S2-MU: KAIROSNAME: C84
2C85 = 0.1U-35-X-S2-MU: KAIROSNAME: C85
2C88 = 0.1U-35-X-S2-MU: KAIROSNAME: C88
2C89 = 10U-10-X-S4-SS: KAIROSNAME: C89
2C90 = 10U-10-X-S4-SS: KAIROSNAME: C90
2C91 = 0.1U-35-X-S2-MU: KAIROSNAME: C91
2C92 = 22U-25-X-S8-MU: KAIROSNAME: C92
2C93 = 22U-25-X-S8-MU: KAIROSNAME: C93
2C94 = 47U-16-T-SC: KAIROSNAME: C94
2C95 = 10U-16-T-SA: KAIROSNAME: C95
2C96 = 10U-10-X-S4-SS: KAIROSNAME: C96
2C97 = 10U-10-X-S4-SS: KAIROSNAME: C97
2C99 = 10U-10-X-S4-SS: KAIROSNAME: C99
2C100 = 0.1U-35-X-S2-MU: KAIROSNAME: C100
2C101 = 10U-10-X-S4-SS: KAIROSNAME: C101
2C102 = 0.1U-35-X-S2-MU: KAIROSNAME: C102
2C105 = 0.1U-35-X-S2-MU: KAIROSNAME: C105
2C106 = 10U-10-X-S4-SS: KAIROSNAME: C106
2C107 = 0.1U-35-X-S2-MU: KAIROSNAME: C107
2C108 = 0.1U-25-X-S4-TY: KAIROSNAME: C108
2C109 = 10U-10-X-S4-SS: KAIROSNAME: C109
2C110 = 10U-10-X-S4-SS: KAIROSNAME: C110
2C111 = 10U-10-X-S4-SS: KAIROSNAME: C111
2C112 = 0.1U-35-X-S2-MU: KAIROSNAME: C112
2C113 = 10U-25-X-S6-MU: KAIROSNAME: C113
2C116 = 22U-25-X-S8-MU: KAIROSNAME: C116
2C117 = 22U-25-X-S8-MU: KAIROSNAME: C117
2C118 = 10U-10-X-S4-SS: KAIROSNAME: C118
2C119 = 0.1U-35-X-S2-MU: KAIROSNAME: C119
2C120 = 47U-16-T-SC: KAIROSNAME: C120
2C121 = 10U-16-T-SA: KAIROSNAME: C121
2C122 = 10U-10-X-S4-SS: KAIROSNAME: C122
2C123 = 10U-10-X-S4-SS: KAIROSNAME: C123
2C124 = 0.1U-35-X-S2-MU: KAIROSNAME: C124
2C125 = 10U-10-X-S4-SS: KAIROSNAME: C125
2C126 = 0.1U-35-X-S2-MU: KAIROSNAME: C126
2C127 = 10U-10-X-S4-SS: KAIROSNAME: C127
2C128 = 0.1U-35-X-S2-MU: KAIROSNAME: C128
2C129 = 10U-10-X-S4-SS: KAIROSNAME: C129
2C130 = 0.1U-25-X-S4-TY: KAIROSNAME: C130
2C131 = 22U-10-T-SA: KAIROSNAME: C131
2C132 = 22U-10-T-SA: KAIROSNAME: C132
2C133 = 22U-10-T-SA: KAIROSNAME: C133
2C134 = 22U-10-T-SA: KAIROSNAME: C134
2C135 = 22U-10-T-SA: KAIROSNAME: C135
2C136 = 10U-10-X-S4-SS: KAIROSNAME: C136
2C137 = 0.1U-25-X-S4-TY: KAIROSNAME: C137
2C138 = 10U-10-X-S4-SS: KAIROSNAME: C138
2C139 = 22U-25-X-S8-MU: KAIROSNAME: C139
2C140 = 47U-16-T-SC: KAIROSNAME: C140
2C141 = 10U-16-T-SA: KAIROSNAME: C141
2C142 = 22U-25-X-S8-MU: KAIROSNAME: C142
2J5 = HDR-1X1-M: KAIROSNAME: J5
2J6 = HDR-2X1-M: KAIROSNAME: J6
2J7 = HDR-2X1-M: KAIROSNAME: J7
2J8 = HDR-2X1-M: KAIROSNAME: J8
2J9 = HDR-2X1-M: KAIROSNAME: J9
2K20 = CU_UA2-12NJ-A-V2: KAIROSNAME: K20
2K21 = CU_UA2-12NJ-A-V2: KAIROSNAME: K21
2K22 2K37 2K38 = CU_UA2-12NJ-A-V2: KAIROSNAME: K22
2K23 = CU_UA2-12NJ-A-V2: KAIROSNAME: K23
2K25 = CU_UA2-12NJ-A-V2: KAIROSNAME: K25
2K26 2K33 = CU_UA2-12NJ-A-V2: KAIROSNAME: K26
2K28 2K30-2K32 = CU_UA2-12NJ-A-V2: KAIROSNAME: K28
2K29 = CU_UA2-12NJ-A-V2: KAIROSNAME: K29
2L1 = L2.2U-1.15A-S2.0X1.6-TDK: KAIROSNAME: L1
2L3 = L2.2U-1.15A-S2.0X1.6-TDK: KAIROSNAME: L3
2L4 = L2.2U-1.15A-S2.0X1.6-TDK: KAIROSNAME: L4
2R48 = 0-5-S4: KAIROSNAME: R48
2R49 = 0-5-S4: KAIROSNAME: R49
2R50 = 0-5-S4: KAIROSNAME: R50
2R51 = 0-5-S4: KAIROSNAME: R51
2R53 = 0-5-S4: KAIROSNAME: R53
2R54 = 0-5-S4: KAIROSNAME: R54
2R55 = 0-5-S4: KAIROSNAME: R55
2R71-2R73 = 2-5-D-2
2R76-2R79 2R81-2R83 = 0-5-S4
2ST3 2ST13-2ST15 = SHORT: KAIROSNAME: ST3
2ST4 = SHORT: KAIROSNAME: ST4
2ST5 2ST16-2ST19 = SHORT: KAIROSNAME: ST5
2ST8 = SHORT: KAIROSNAME: ST8
2ST11 = SHORT: KAIROSNAME: ST11
2ST12 = SHORT: KAIROSNAME: ST12
S2_1V3 = TP03-D: KAIROSNAME: S0_TP_VD3
S2_GND1 = TP03-D: KAIROSNAME: S0_GND1
S2_GND2 = TP03-D: KAIROSNAME: S0_GND2
S2_GND3 = TP03-D: KAIROSNAME: S0_GND3
S2_GND4 = TP03-D: KAIROSNAME: S0_GND4
S2_VD33_ALL1 = TP03-D: KAIROSNAME: S0_VD33_ALL1
S2_VDD09 = TP03-D: KAIROSNAME: S0_VDD09
S2_VDD18_A = TP03-D: KAIROSNAME: S0_VDD18_A
S2_VDD18_D = TP03-D: KAIROSNAME: S0_VDD18_D

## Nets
AGND: 2BD34.2 2BD35.2 2C1.1 2C3.2 2C4.1 2C5.2 2C8.2 2C9.1 2C10.2 2C11.1 2C12.2 2C15.2 2C16.1 2C19.2 2D1.2(CATHODE_D2) 2D2.2(CATHODE_D2) 2D3.2(CATHODE_D2) 2SMP1.G1 2SMP1.G2 2SMP1.G3 2SMP1.G4 2SMP1.G5 2SMP1.G6 2SMP1.G7 2SMP1.G8 2SMP1.G9 2SMP2.G1 2SMP2.G2 2SMP2.G3 2SMP2.G4 2SMP2.G5 2SMP2.G6 2SMP2.G7 2SMP2.G8 2SMP2.G9 2SMP3.G1 2SMP3.G2 2SMP3.G3 2SMP3.G4 2SMP3.G5 2SMP3.G6 2SMP3.G7 2SMP3.G8 2SMP3.G9 2U1.2(GND) 2U2.2(GND) ; also on sheet 2 5 11 14 17 20 23
DGND: 2BD34.1 2BD35.1 2C17.1 2C18.1 2C20.2 2C21.2 2C22.2 2C23.1 2C24.2 2C25.1 2C38.1 2C39.2 2C40.1 2C41.2 2C44.2 2C45.2 2C46.2 2C47.2 2C48.2 2C49.2 2C52.2 2C53.2 2C54.2 2C55.2 2C56.2 2C57.2 2C58.2 2C59.2 2C60.2 2C61.2 2C62.2 2C63.2 2C64.2 2C65.2 2C66.2 2C67.2 2C68.2 2C69.2 2C70.2 2C71.2 2C72.2 2C73.2 2C74.2 2C75.2 2C76.2 2C77.2 2C78.2 2C79.2 2C83.2 2C84.2 2C85.2 2C88.2 2C89.2 2C90.2 2C91.2 2C92.2 2C93.2 2C94.2 2C95.2 2C96.2 2C97.2 2C98.2 2C99.2 2C100.2 2C101.2 2C102.2 2C105.2 2C106.2 2C107.2 2C108.2 2C109.2 2C110.2 2C111.2 2C112.2 2C113.1 2C116.2 2C117.2 2C118.2 2C119.2 2C120.2 2C121.2 2C122.2 2C123.2 2C124.2 2C125.2 2C126.2 2C127.2 2C128.2 2C129.2 2C130.2 2C131.2 2C132.2 2C133.2 2C134.2 2C135.2 2C136.2 2C137.2 2C138.2 2C139.2 2C140.2 2C141.2 2C142.2 2C143.1 2C144.1 2C145.1 2C146.1 2C147.1 2C148.1 2C149.1 2C150.1 2C152.2 2C153.2 2J1.2 2J2.2 2J3.2 2J4.8 2R18.1 2R22.2 2R23.2 2R25.2 2R26.2 2R33.1 2R42.2 2R43.2 2R49.2 2R51.2 2R54.2 2R62.2 2R71.2 2R72.2 2R73.2 2ST5.2 2ST16.2 2ST17.2 2ST18.2 2ST19.2 2U3.4(GND) 2Y1.2 2Y1.4 S2_GND1.1(TP) S2_GND2.1(TP) S2_GND3.1(TP) S2_GND4.1(TP) SITE2.4(GND_SPS_DCORE) SITE2.30(GND) SITE2.74(GND_SPS_MEM) SITE2.99(GND_SPS_AUD) SITE2.EP(EPAD) SITE2.G1 SITE2.G2 SITE2.G3 SITE2.G4 SITE2.G5 SITE2.G6 SITE2.G7 SITE2.G8 SITE2.G9 SITE2.G10 SITE2.G11 SITE2.G12 SITE2.G13 SITE2.G14 SITE2.G15 SITE2.G16 SITE2.G17 SITE2.G18 SITE2.G19 SITE2.G20 SITE2.G21 SITE2.G22 SITE2.G23 SITE2.G24 SITE2.G25 SITE2.G26 SITE2.G27 SITE2.G28 SITE2.G29 SITE2.G30 SITE2.G31 SITE2.G32 SITE2.G33 ; also on sheet 2 3 4 5 6 7 11 12 13 14 15 16 17 18 19 20 21 22 23 24 25 26 27 29 30 32 34 37 39
S2_1_AOUT_LN: 2K10.4 2R45.1 2R67.1 2R68.1
S2_1_AOUT_LP: 2K10.5 2R69.1 2R70.1 2R75.1
S2_1_AOUT_RN: 2K14.4 2R47.1 2R63.1 2R64.1
S2_1_AOUT_RP: 2K14.5 2R65.1 2R66.1 2R74.1
S2_1_SPI_CLK: 2R15.1 2U3.6(SCLK)
S2_1_SPI_CS: 2R10.2 2U3.1(CS#)
S2_1_SPI_DATA0: 2R17.1 2U3.5(SI/SIO0)
S2_1_SPI_DATA1: 2R11.2 2U3.2(SO/SIO1)
S2_1_SPI_DATA2: 2R14.2 2R16.2 2R18.2 2U3.3(WP#/SIO2)
S2_1_SPI_DATA3: 2R12.1 2R13.1 2U3.7(RST#/SIO3)
S2_1_VDD09: 2BD1.1 2BD2.1 2BD37.1 2C60.1 2R48.2 2R76.1 2R77.1 2R78.1 2R79.1 2ST13.2
S2_1_VDD18_A: 2K26.2 2K26.5 2R50.1 S2_1V3.1(TP)
S2_1_VDD18_D: 2C113.2 2R53.2 2R81.1 2R82.1 2R83.1 2ST15.1
S2_2_AOUT_LN: 2K12.4 2R68.2
S2_2_AOUT_LP: 2K12.5 2R69.2
S2_2_AOUT_RN: 2K15.4 2R64.2
S2_2_AOUT_RP: 2K15.5 2R65.2
S2_2_VDD18_A: 2BD16.1 2BD17.1 2BD19.1 2BD20.1 2C89.1 2R50.2
S2_ATX_VD0V9: 2C65.1 2C66.1 2K21.6 2ST3.2 ; also on sheet 27
S2_ATX_VD1V8: 2J7.1 2J8.1 2J9.1 ; also on sheet 27
S2_ATX_VD33: 2BD33.1 2C131.1 2C132.1 2C133.1 2C134.1 2C135.1 2J6.2 ; also on sheet 27
S2_AVCC_DRV: 2C75.1 2C110.1 2R55.2 2ST14.1 SITE2.53(AVCC_DRV)
S2_CHIP_EN_1: 2R34.2 2SW5.1
S2_DPS_F001: 2C120.1 2C121.1 2J9.2 2K29.6 2ST11.2
S2_DPS_F002: 2C92.1 2C93.1 2C94.1 2C95.1 2J8.2 2K26.6 2ST8.2
S2_DPS_F004: 2C140.1 2C141.1 2J7.2 2K20.6 2ST12.2
S2_DPS_F006: 2C68.1 2C69.1 2C70.1 2C71.1 2C72.1 2K23.3 2K23.6 2ST4.2 S2_VD33_ALL1.1(TP)
S2_DPS_GS001: 2ST19.1
S2_DPS_GS002: 2ST18.1
S2_DPS_GS003-1: 2ST16.1
S2_DPS_GS004: 2ST17.1
S2_DPS_GS006: 2ST5.1
S2_DPS_S001: 2ST11.1
S2_DPS_S002: 2ST8.1
S2_DPS_S003-1: 2ST3.1
S2_DPS_S004: 2ST12.1
S2_DPS_S006: 2ST4.1
S2_HSDM: 2K5.8 SITE2.79(HSDM)
S2_HSDP: 2K5.2 SITE2.78(HSDP)
S2_LPC_001: 2K36.7
S2_LPC_002: 2K36.2
S2_LPC_003: 2K11.2
S2_LPC_005: 2K14.2
S2_LPC_006: 2K18.4
S2_LPC_007: 2K1.4
S2_LPC_008: 2K35.2
S2_LPC_009: 2K38.3
S2_LPC_010: 2K34.7
S2_LPC_012: 2K37.3
S2_LPC_013+: 2K5.3 2K7.2
S2_LPC_013-: 2K5.7 2K7.8
S2_LPC_016: 2K2.5
S2_LPC_017: 2K35.7
S2_LPC_019: 2K12.2
S2_LPC_021: 2K1.5
S2_LPC_022: 2K15.2
S2_LPC_023: 2K3.4
S2_LPC_024: 2J4.2 2R35.1 SITE2.69(UART2_TXD/TEST_MODE_SEL/DMIC0_CLK/GPIOF_1/PB[22])
S2_LPC_025: 2J4.1 2R34.1 SITE2.71(CHIP_EN)
S2_LPC_026: 2K2.4
S2_LPC_027: 2K10.2
S2_LPC_028: 2K10.7
S2_LPC_029: 2K13.7
S2_LPC_030: 2K16.2
S2_LPC_032: 2K15.7
S2_LPC_033: 2K14.7
S2_LPC_034: 2K18.5
S2_LPC_035: 2K12.7
S2_LPC_036: 2K34.2
S2_LPC_038: 2K13.2
S2_LPC_039: 2K3.5
S2_LPC_040: 2K11.7
S2_LPC_041: 2J4.3 2R36.1 SITE2.68(UART2_RXD/BOOT_SEL/DMIC0_DATA/GPIOF_0/PB[21])
S2_LPC_042: 2C18.2 SITE2.50(MIC_BIAS2/GPIOC_13/PA[31])
S2_LPC_043: 2K33.3
S2_LPC_044: 2J4.5 2R39.1 SITE2.58(I2S3_DOUT1/DMIC_DATA2/ICFG1/GPIOD_4/PB[11])
S2_LPC_045: 2K39.3
S2_LPC_046: SITE2.67(I2S2_DIN3/I2S3_DOUT3/SPK_CLK/SPI0_CS/GPIOE_6/PB[20])
S2_LPC_047: 2J4.7 2R41.1 SITE2.18(GPIOB_7/PA[16]/ICFG3/SPI0_CS/UART0_RTS/HP_I2C2_SCL/ANT_SEL_N)
S2_LPC_048: 2K6.4
S2_LPC_049: SITE2.8(GPIOA_5/PA[5]/TOUCH5/ADC5/UART1_TXD/SPI1_MOSI/PWM4)
S2_LPC_050: SITE2.7(GPIOA_4/PA[4]/TOUCH4/ADC4/UART1_RXD/SPI1_MISO/PWM3/HP_I2C1_SCL)
S2_LPC_051: 2C17.2 SITE2.49(MIC_BIAS1/GPIOC_12/PA[30])
S2_LPC_052: 2C21.1 SITE2.48(AVCC)
S2_LPC_053: 2J4.4 2R37.1 SITE2.57(I2S3_DOUT0/DMIC_DATA1/ICFG0/BT_LOG/GPIOD_3/PB[10])
S2_LPC_054: 2K6.5
S2_LPC_055: SITE2.10(VBAT_MEAS)
S2_LPC_057: 2K9.4
S2_LPC_058: 2J4.6 2R40.1 SITE2.17(GPIOB_6/PA[15]/ICFG2/SPI0_CLK/UART0_CTS/HP_I2C2_SDA/ANT_SEL_P)
S2_LPC_059: 2K39.6
S2_LPC_060: SITE2.66(I2S2_DIN2/I2S3_DOUT2/SPK_DATA/SPI0_CK/GPIOE_5/PB[19])
S2_LPC_A_015: 2K8.4
S2_LPC_A_020: 2K8.5
S2_LPC_B_031: 2K4.4
S2_LPC_B_037: 2K4.5
S2_LX_AUD: 2K20.3 SITE2.100(LX_AUD)
S2_LX_AUD_CH_1: 2K20.4 2K38.2
S2_LX_AUD_CH_2: 2K38.4 2ST14.2
S2_LX_DCORE: 2K21.3 SITE2.3(LX_DCORE)
S2_LX_DCORE_CH: 2K21.4 2K37.2
S2_LX_MEM: 2K29.3 SITE2.75(LX_MEM)
S2_LX_MEM_CH_1: 2K29.4 2K33.2
S2_LX_MEM_CH_2: 2K33.4 2ST15.2
S2_MIPITX_CKN: 2K36.6 SITE2.82(MIPITX_CKN)
S2_MIPITX_CKP: 2K36.3 SITE2.83(MIPITX_CKP)
S2_MIPITX_DATAN_0: 2K34.6 SITE2.85(MIPITX_DATAN_0)
S2_MIPITX_DATAN_1: 2K35.6 SITE2.80(MIPITX_DATAN_1)
S2_MIPITX_DATAP_0: 2K34.3 SITE2.86(MIPITX_DATAP_0)
S2_MIPITX_DATAP_1: 2K35.3 SITE2.81(MIPITX_DATAP_1)
S2_PA2: 2K18.3 SITE2.5(GPIOA_2/PA[2]/TOUCH2/ADC2/UART0_RXD/SPI1_CS)
S2_PA3: 2K18.6 SITE2.6(GPIOA_3/PA[3]/TOUCH3/ADC3/UART0_TXD/SPI1_CLK/LEDC/HP_I2C1_SDA)
S2_PA9_CH: 2K39.2 SITE2.12(GPIOB_0/PA[9])
S2_PA10_CH: 2K39.7 SITE2.13(GPIOB_1/PA[10])
S2_PA13: 2K6.3 SITE2.15(GPIOB_4/PA[13]/SWD_DATA/SPI0_MOSI/UART0_RXD/HP_I2C1_SDA)
S2_PA13_UART_RX: 2K6.2 2R27.1
S2_PA13_UART_RX_1: 2J2.3 2R27.2
S2_PA14: 2K6.6 SITE2.16(GPIOB_5/PA[14]/SWD_CLK/SPI0_MISO/UART0_TXD/HP_I2C1_SCL)
S2_PA14_UART_TX: 2K6.7 2R28.1
S2_PA14_UART_TX_1: 2J2.4 2R28.2
S2_PA15_1: 2R40.2 2SW5.6
S2_PA16_1: 2R41.2 2SW5.7
S2_PA20: 2K15.6 SITE2.45(MIC1_P/GPIOC_2/PA[20])
S2_PA21: 2K15.3 SITE2.46(MIC1_N/GPIOC_3/PA[21])
S2_PA22: 2K11.6 SITE2.43(MIC2_P/GPIOC_4/PA[22])
S2_PA23: 2K11.3 SITE2.44(MIC2_N/GPIOC_5/PA[23])
S2_PA24: 2K12.6 SITE2.41(MIC3_P/I2C_SDA/GPIOC_6/PA[24])
S2_PA25: 2K12.3 SITE2.42(MIC3_N/I2C_SCL/GPIOC_7/PA[25])
S2_PA28: 2K13.6 SITE2.39(MIC5_P/ANT_SEL_P/GPIOC_10/PA[28])
S2_PA29: 2K13.3 SITE2.40(MIC5_N/ANT_SEL_N/GPIOC_11/PA[29])
S2_PB3: 2K10.6 SITE2.52(AOUT_LP/GPIOC_17/PB[3])
S2_PB3_AOUT_LP_2: 2K13.5 2R70.2
S2_PB4: 2K10.3 SITE2.51(AOUT_LN/GPIOC_18/PB[4])
S2_PB4_AOUT_LN_2: 2K13.4 2R67.2
S2_PB5: 2K14.6 SITE2.54(AOUT_RP/GPIOC_19/PB[5])
S2_PB5_AOUT_RP_2: 2K11.5 2R66.2
S2_PB6: 2K14.3 SITE2.55(AOUT_RN/GPIOC_20/PB[6])
S2_PB6_AOUT_RN_2: 2K11.4 2R63.2
S2_PB10_1: 2R37.2 2SW5.4
S2_PB11_1: 2R39.2 2SW5.5
S2_PB21_1: 2R36.2 2SW5.3
S2_PB22_1: 2R35.2 2SW5.2
S2_PB23: 2C144.2 2K4.3 2R57.1 SITE2.72(UART_LOG_RXD/OTP_BYPASS/GPIOF_2/PB[23])
S2_PB23_1: 2R57.2 2SW6.1
S2_PB23_SICK: 2K4.2 2R20.1
S2_PB23_SICK_1: 2J1.3 2R20.2
S2_PB24: 2C143.2 2K4.6 2R58.1 SITE2.73(UART_LOG_TXD/UART_DOWNLOAD/GPIOF_3/PB[24])
S2_PB24_1: 2R58.2 2SW6.2
S2_PB24_SIDD: 2K4.7 2R21.1
S2_PB24_SIDD_1: 2J1.4 2R21.2
S2_PB25: 2K8.3 2R59.1 SITE2.96(SPI0_CLK/SWD_CLK/SD_D2/ICFG2/GPIOG_0/PB[25])
S2_PB25_1: 2R59.2 2SW6.3
S2_PB25_I2C_SCL: 2K8.2 2R31.1
S2_PB25_I2C_SCL_1: 2J3.3 2R31.2
S2_PB26: 2K8.6 2R60.1 SITE2.97(SPI0_CS/SWD_DATA/SD_D3/ICFG3/GPIOG_1/PB[26])
S2_PB26_1: 2R60.2 2SW6.4
S2_PB26_I2C_SDA: 2K8.7 2R32.1
S2_PB26_I2C_SDA_1: 2J3.4 2R32.2
S2_RF_A: 2C13.1 2C14.1 2C15.1 2D3.1(CATHODE_D1) 2SMP3.1
S2_RF_G: 2C6.1 2C7.1 2C8.1 2D2.1(CATHODE_D1) 2SMP2.1
S2_RFIN_A: 2C16.2 2R9.1 SITE2.29(RFIN_A/GND_(<750um))
S2_RFIN_G: 2C9.2 2R5.1 SITE2.31(RFIN_G/GND)
S2_RFIO_A: 2C11.2 2R6.1 SITE2.28(RFIO_A__(<750um))
S2_RFIO_BT: 2C1.2 2R1.1 SITE2.37(RFIO_BT)
S2_RFIO_G: 2C4.2 2R2.1 SITE2.32(RFIO_G)
S2_RREF_MEM: 2K9.3 2R43.1 SITE2.60(RREF_MEM)
S2_SPI_CLK: 2K1.7 2R15.2
S2_SPI_CLK/PB28: 2K1.6 SITE2.90(SPI_FLASH_CLK/SD_CLK/GPIOG_3/PB[28])
S2_SPI_CS: 2K3.2 2R10.1
S2_SPI_CS/PC0: 2K3.3 SITE2.95(SPI_FLASH_CS/UART1_CTS/SD_CD/GPIOG_7/PC[0])
S2_SPI_D0/PB29: 2K1.3 SITE2.91(SPI_FLASH_DATA0/UART1_RXD/SD_D0/GPIOG_4/PB[29])
S2_SPI_D1/PB31: 2K3.6 SITE2.94(SPI_FLASH_DATA1/UART1_RTS/SD_WP/GPIOG_6/PB[31])
S2_SPI_D2/PB30: 2K2.6 SITE2.92(SPI_FLASH_DATA2/UART1_TXD/SD_D1/GPIOG_5/PB[30])
S2_SPI_D3/PB27: 2K2.3 SITE2.89(SPI_FLASH_DATA3/SD_CMD/GPIOG_2/PB[27])
S2_SPI_DATA0: 2K1.2 2R17.2
S2_SPI_DATA1: 2K3.7 2R11.1
S2_SPI_DATA2: 2K2.7 2R16.1
S2_SPI_DATA3: 2K2.2 2R13.2
S2_U1_VC1: 2K39.5 2U1.4(VCTL)
S2_U2_VC1: 2K39.4 2U2.4(VCTL)
S2_VA09_MIPI: 2BD37.2 2C152.1 SITE2.84(VA09_MIPI/VA09_CK/VA09_DA)
S2_VA09_PLL: 2BD1.2 2C44.1 SITE2.11(VA09_PLL/VD09_CORE0)
S2_VA09_USB: 2BD2.2 2C45.1 SITE2.77(VA09_USB)
S2_VA13_AFE: 2BD20.2 2C88.1 SITE2.19(VA13_AFE)
S2_VA13_SYN: 2BD16.2 2C78.1 SITE2.23(VR13_SYN)
S2_VA33_SYN: 2BD13.2 2C64.1 SITE2.24(VR33_SYN)
S2_VA33_XTAL: 2BD5.2 2C48.1 SITE2.20(VA33_XTAL)
S2_VD09_CORE1: 2C47.1 2R76.2 SITE2.56(VD09_CORE1/VD09MEM0)
S2_VD09_CORE2: 2C49.1 2R77.2 SITE2.64(VD09_CORE2/VD09_MEM1)
S2_VD09_CORE3: 2C54.1 2R78.2 SITE2.87(VD09_CORE3/VA09_PLL)
S2_VD09_CORE4: 2C58.1 2R79.2 SITE2.98(VD09_CORE4)
S2_VD13_FE: 2BD19.2 2C85.1 SITE2.36(VD13_FE)
S2_VD13_RF: 2BD17.2 2C79.1 SITE2.25(VD13_RF)
S2_VD33_ALL: 2BD3.1 2BD5.1 2BD7.1 2BD9.1 2BD11.1 2BD12.1 2BD13.1 2BD15.1 2BD18.1 2BD21.1 2BD22.1 2BD23.1 2BD28.1 2BD29.1 2BD30.1 2BD31.1 2BD32.1 2BD36.1 2C67.1 2C96.1 2C101.1 2C122.1 2C129.1 2J5.1 2J6.1 2K23.2 2K23.7
S2_VD33_CM_BT: 2BD21.2 2C90.1 2C91.1 SITE2.35(VD33_CM_BT)
S2_VD33_EX_FLASH: 2BD32.2 2C22.1 2C127.1 2C128.1 2R12.2 2R14.1 2U3.8(VCC)
S2_VD33_IO0: 2BD7.2 2C52.1 SITE2.9(VA33_PLL/VD33_IO0)
S2_VD33_IO2: 2BD9.2 2C56.1 SITE2.59(VD33_IO2/VD33_MEM)
S2_VD33_IO3: 2BD11.2 2C59.1 SITE2.70(VD33_IO3/VDD_IO4/VA33_USB)
S2_VD33_IO6: 2BD12.2 2C61.1 SITE2.88(VD33_IO6/VDD33_IO5/VD33_FLASH)
S2_VD33_SPS_AUD: 2BD30.2 2C123.1 2C124.1 SITE2.1(VD33_SPS_AUD)
S2_VD33_SPS_DCORE: 2BD28.2 2C111.1 2C112.1 SITE2.2(VD33_SPS_DCORE)
S2_VD33_SPS_MEM: 2BD31.2 2C125.1 2C126.1 SITE2.76(VD33_SPS_MEM)
S2_VD33PA_A: 2BD23.2 2C99.1 2C100.1 SITE2.27(VD33PA_A)
S2_VD33PA_BT: 2BD18.2 2C83.1 2C84.1 SITE2.38(VD33PA_BT)
S2_VD33PA_G: 2BD15.2 2C76.1 2C77.1 SITE2.33(VD33PA_G)
S2_VD33PAD_A: 2BD22.2 2C97.1 2C98.1 SITE2.26(VD33PAD_A)
S2_VD33PAD_G: 2BD36.2 2C73.1 2C74.1 SITE2.34(VD33PAD_G)
S2_VD1833_IO1: 2BD3.2 2C46.1 SITE2.14(VD1833_IO1)
S2_VD1833_SDIO: 2BD29.2 2C118.1 2C119.1 SITE2.93(VD1833_SDIO)
S2_VD_MEM0: 2C102.1 2R81.2 SITE2.61(VD_MEM0)
S2_VD_MEM1: 2C105.1 2R82.2 SITE2.62(VD_MEM1)
S2_VD_MEM2: 2C107.1 2R83.2 SITE2.65(VD_MEM2)
S2_VDD09: 2K22.2 2K22.5 2K31.4 2R48.1 S2_VDD09.1(TP)
S2_VDD09_CH: 2K37.4 2ST13.1
S2_VDD18_A: 2K25.2 2K25.5 2K26.3 2K32.4 2R55.1 S2_VDD18_A.1(TP)
S2_VDD18_D: 2K28.2 2K28.5 2K30.4 2R29.2 2R53.1 S2_VDD18_D.1(TP)
S2_VDD33: 2BD33.2 2C130.1 2R19.1 2R24.1 2R30.1 2R38.2 2R61.2 2U1.6(VDD) 2U2.6(VDD)
S2_VDD33_J1: 2J1.1 2R19.2
S2_VDD33_J2: 2J2.1 2R24.2
S2_VDD33_J3: 2J3.1 2R30.2
S2_VREF_DRAM: 2C153.1 2K16.3 SITE2.63(VREF_DRAM/NC(PSRAM))
S2_XI: 2C25.2 2Y1.1 SITE2.22(XI)
S2_XO: 2C23.2 2Y1.3 SITE2.21(XO)
S3_LPC_009: 2K38.6
S3_LPC_012: 2K37.6
S3_LPC_043: 2K33.6
S3_LX_AUD_CH_1: 2K38.7 ; also on sheet 13
S3_LX_AUD_CH_2: 2K38.5 ; also on sheet 13
S3_LX_DCORE_CH: 2K37.7 ; also on sheet 13
S3_LX_MEM_CH_1: 2K33.7 ; also on sheet 13
S3_LX_MEM_CH_2: 2K33.5 ; also on sheet 13
S3_VDD09_CH: 2K37.5 ; also on sheet 13
S0123_CBIT_001: 2K7.9(V-) ; also on sheet 2 5 11
S0123_CBIT_002: 2K37.8(V-) ; also on sheet 2 4
S0123_CBIT_003: 2K6.8(V-) ; also on sheet 2 5 11
S0123_CBIT_004: 2K2.8(V-) ; also on sheet 2 5 11
S0123_CBIT_005: 2K3.8(V-) ; also on sheet 2 5 11
S0123_CBIT_006: 2K35.8(V-) ; also on sheet 2 3 6 12
S0123_CBIT_007: 2K33.8(V-) ; also on sheet 2 4
S0123_CBIT_008: 2K30.8(V-) ; also on sheet 2 4 7 13
S0123_CBIT_009: 2K32.8(V-) ; also on sheet 2 4 7 13
S0123_CBIT_010: 2K31.8(V-) ; also on sheet 2 4 7 13
S0123_CBIT_011: 2K29.8(V-) ; also on sheet 2 4 7 13
S0123_CBIT_012: 2K28.8(V-) ; also on sheet 2 4 7 13
S0123_CBIT_013: 2K8.8(V-) ; also on sheet 2 5 11
S0123_CBIT_014: 2K26.8(V-) ; also on sheet 2 4 7 13
S0123_CBIT_015: 2K34.8(V-) ; also on sheet 2 3 6 12
S0123_CBIT_016: 2K16.8(V-) ; also on sheet 2 5 11
S0123_CBIT_017: 2K21.8(V-) ; also on sheet 2 4 7 13
S0123_CBIT_018: 2K18.8(V-) ; also on sheet 2 3 6 12
S0123_CBIT_019: 2K22.8(V-) ; also on sheet 2 4 7 13
S0123_CBIT_020: 2K9.8(V-) ; also on sheet 2 5 11
S0123_CBIT_022: 2K19.8(V-) ; also on sheet 2 3 6 12
S0123_CBIT_023: 2K23.8(V-) ; also on sheet 2 4 7 13
S0123_CBIT_024: 2K20.8(V-) ; also on sheet 2 4 7 13
S0123_CBIT_025: 2K13.8(V-) ; also on sheet 2 3 6 12
S0123_CBIT_026: 2K14.8(V-) ; also on sheet 2 3 6 12
S0123_CBIT_027: 2K15.8(V-) ; also on sheet 2 3 6 12
S0123_CBIT_028: 2K25.8(V-) ; also on sheet 2 4 7 13
S0123_CBIT_029: 2K10.8(V-) ; also on sheet 2 3 6 12
S0123_CBIT_030: 2K11.8(V-) ; also on sheet 2 3 6 12
S0123_CBIT_031: 2K12.8(V-) ; also on sheet 2 3 6 12
S0123_CBIT_032: 2K39.8(V-) ; also on sheet 2 5 11
S0123_CBIT_033: 2K1.8(V-) ; also on sheet 2 5 11
S0123_CBIT_034: 2K38.8(V-) ; also on sheet 2 4
S0123_CBIT_035: 2K5.9(V-) ; also on sheet 2 5 11
S0123_CBIT_036: 2K36.8(V-) ; also on sheet 2 3 6 12
S0123_CBIT_037: 2K4.8(V-) ; also on sheet 2 5 11
VP12: 2K1.1(V+) 2K2.1(V+) 2K3.1(V+) 2K4.1(V+) 2K5.1(V+) 2K6.1(V+) 2K7.1(V+) 2K8.1(V+) 2K9.1(V+) 2K10.1(V+) 2K11.1(V+) 2K12.1(V+) 2K13.1(V+) 2K14.1(V+) 2K15.1(V+) 2K16.1(V+) 2K18.1(V+) 2K19.1(V+) 2K20.1(V+) 2K21.1(V+) 2K22.1(V+) 2K23.1(V+) 2K25.1(V+) 2K26.1(V+) 2K28.1(V+) 2K29.1(V+) 2K30.1(V+) 2K31.1(V+) 2K32.1(V+) 2K33.1(V+) 2K34.1(V+) 2K35.1(V+) 2K36.1(V+) 2K37.1(V+) 2K38.1(V+) 2K39.1(V+) ; also on sheet 2 3 4 5 6 7 11 12 13 14 15 16 17 18 19 20 21 22 23 24 25 26 27 29 38
N27448585: 2C10.1 2R5.2 2U1.3(RF2)
N27448591: 2C7.2 2U1.5(ANT)
N27448594: 2R4.1 2U1.1(RF1)
N27448645: 2C6.2 2R3.2
N27448654: 2C19.1 2R9.2 2U2.1(RF1)
N27448661: 2C14.2 2U2.5(ANT)
N27448668: 2C12.1 2R6.2 2R7.1 2R8.2
N27448670: 2C13.2 2R7.2
N27448689: 2BD27.2 2C24.1 2K16.4
N27448699: 2K5.6 2R22.1
N27448701: 2K5.4 2R25.1
N27448704: 2R8.1 2U2.3(RF2)
N27448710: 2C5.1 2R2.2 2R3.1 2R4.2
N27448738: 2C2.1 2C3.1 2R1.2
N27448743: 2C2.2 2D1.1(CATHODE_D1) 2SMP1.1
N27448861: 2K7.6 2R23.1
N27448862: 2K7.4 2R26.1
N27448867: 2BD27.1 2R29.1 2R33.2
N27448994: 2C20.1 SITE2.47(VREF_AUDIO)
N27452593: 2K18.2 2K19.3
N27452594: 2K18.7 2K19.6
N27452597: 2C39.1 2K19.4
N27452598: 2C38.2 2K19.2
N27452601: 2C41.1 2K19.5
N27452602: 2C40.2 2K19.7
N27452633: 2R47.2 2R74.2
N27452715: 2R45.2 2R75.2
N27452731: 2C145.2 2K34.4
N27452732: 2C146.2 2K34.5
N27452739: 2C147.2 2K35.4
N27452740: 2C148.2 2K35.5
N27452743: 2C149.2 2K36.4
N27452744: 2C150.2 2K36.5
N27453831: 2K21.2 2L1.1
N27453861: 2K29.2 2L3.1
N27453862: 2C106.1 2C108.1 2C109.1 2K28.3 2L3.2
N27453873: 2K28.4 2R54.1
N27453877: 2C116.1 2C117.1 2K28.6 2K29.5
N27453900: 2C53.1 2C55.1 2C57.1 2K22.3 2L1.2
N27453912: 2K22.4 2R49.1
N27453916: 2C62.1 2C63.1 2K21.5 2K22.6
N27454031: 2K20.2 2L4.1
N27454032: 2C136.1 2C137.1 2C138.1 2K25.3 2L4.2
N27454043: 2K25.4 2R51.1
N27454045: 2C139.1 2C142.1 2K20.5 2K25.6
N27454151: 2K30.3 2R71.1
N27454153: 2K31.3 2R72.1
N27454155: 2K32.3 2R73.1
N27679333: 2R61.1 2SW6.6
N27679337: 2R62.1 2SW6.5
N27679417: 2R38.1 2SW5.10
N27679421: 2R42.1 2SW5.9

Not connected (* = marked no-connect by the designer): 2K7 3* 7*; 2K9 2* 5* 6* 7*; 2K16 5* 6* 7*; 2K20 7*; 2K21 7*; 2K22 7*; 2K23 4* 5*; 2K25 7*; 2K26 4* 7*; 2K28 7*; 2K29 7*; 2K30 2* 5* 6* 7*; 2K31 2* 5* 6* 7*; 2K32 2* 5* 6* 7*; 2SW5 8*; SITE2 GH1* GH2* GH3* GH4* NUT1* NUT2* NUT3* NUT4*

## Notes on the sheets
sheet 8
- WIFI/BT_RF
- place by Z-shape
- R3 and R4 Share PAD,
  Default R3
- C6 and C7 Share PAD,
  Default C6
- place by Z-shape
- place by Z-shape
- R7 and R8 Share PAD,
  Default R7
- C13 and C14 Share PAD,
  Default C13
- place by Z-shape
- place by Z-shape
- GND Shielding
- FLASH
- RF SW Channel  and PA9.10 share one Channel
- GND Shielding
- Mark On Board
- GND Shielding
- Debug
- 1.S0_VDD33
- 2.GND
- 3.S0_SICK
- DSSC
- 4.S0_SIDD
- SIC
- USB
- GND Shielding
- Mark On Board
- Debug
- 1.S0_VDD33
- 2.GND
- 3.S0_UART_RX
- 4.S0_UART_TX
- DIFF 90ohm
- UART
- DIFF 90ohm
- Debug
- Mark On Board
- XTAL
- VREF_DRAM
- GND Shielding
- 1.S0_VDD33
- Close To DUT
- 2.GND
- 3.S0_I2C_SCL
- DSSC
- 4.S0_I2C_SDA
- BT_I2C
- GND Shielding
- Mark On Board
- 1.S0_CHIP_EN
- 2.S0_PB22_TEST_MODE_SEL
- 3.S0_PB21_BOOT_SEL_FLASH
- 4.S0_PB10/ICFG0
- 5.S0_PB11/ICFG1
- 6.S0_PA15/ICFG2
- 7.S0_PA16/ICFG3
- 8.NC
- RREF
- Close To DUT
- Close to Relay
sheet 9
- AUDIO ADC Test
- MIPI Test
- GND Shielding
- GND Shielding
- CAP TOUCH Test
- GND Shielding
sheet 10
- CLOSE TO DUT
- POWER_VD09
- POWER_VD1833
- CLOSE TO DUT
- 110mA
- 5mA
- 33mA
- C48 TOP
- 20mA
- RELAY 2 SITE share
- 102mA
- 35mA
- 105mA
- 35mA
- 112mA
- 25mA
- 50mA
- Mark On Board : S0_VDD09
- C58 TOP
- 30mA
- 50mA
- 10mA
- C64 TOP
- 200mA
- CLOSE TO DUT
- 200mA
- POWER_VD18_AUD
- CLOSE TO DUT
- Mark On Board : S0_VDD18_A
- 200mA
- 100mA
- C75 TOP
- 50mA
- Mark On Board : S0_VDD33
- CLOSE TO DUT
- CLOSE TO DUT
- 45mA
- 60mA
- C78 TOP
- 80mA
- C79 TOP
- 45mA
- C97,C98 TOP
- RELAY 2 SITE share
- 300mA
- 25mA
- C88 TOP
- C99,C100 TOP
- POWER_VD18_DDR
- RELAY 2 SITE share
- CLOSE TO DUT
- CLOSE TO DUT
- 155mA
- 62mA
- C111,C112 TOP
- 62mA
- 30mA
- 62mA
- Mark On Board : S0_VDD18_D
- C107 TOP
- 107mA
- C123,C124 TOP
- 160mA
- C125,C126 TOP
- 50mA
- Calibration Loading SCH
